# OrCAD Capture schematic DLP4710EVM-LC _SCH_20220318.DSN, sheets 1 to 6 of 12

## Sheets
1 P08: DLPC3479_VDD,VSS: size D; title: DLP4710EVM-LC
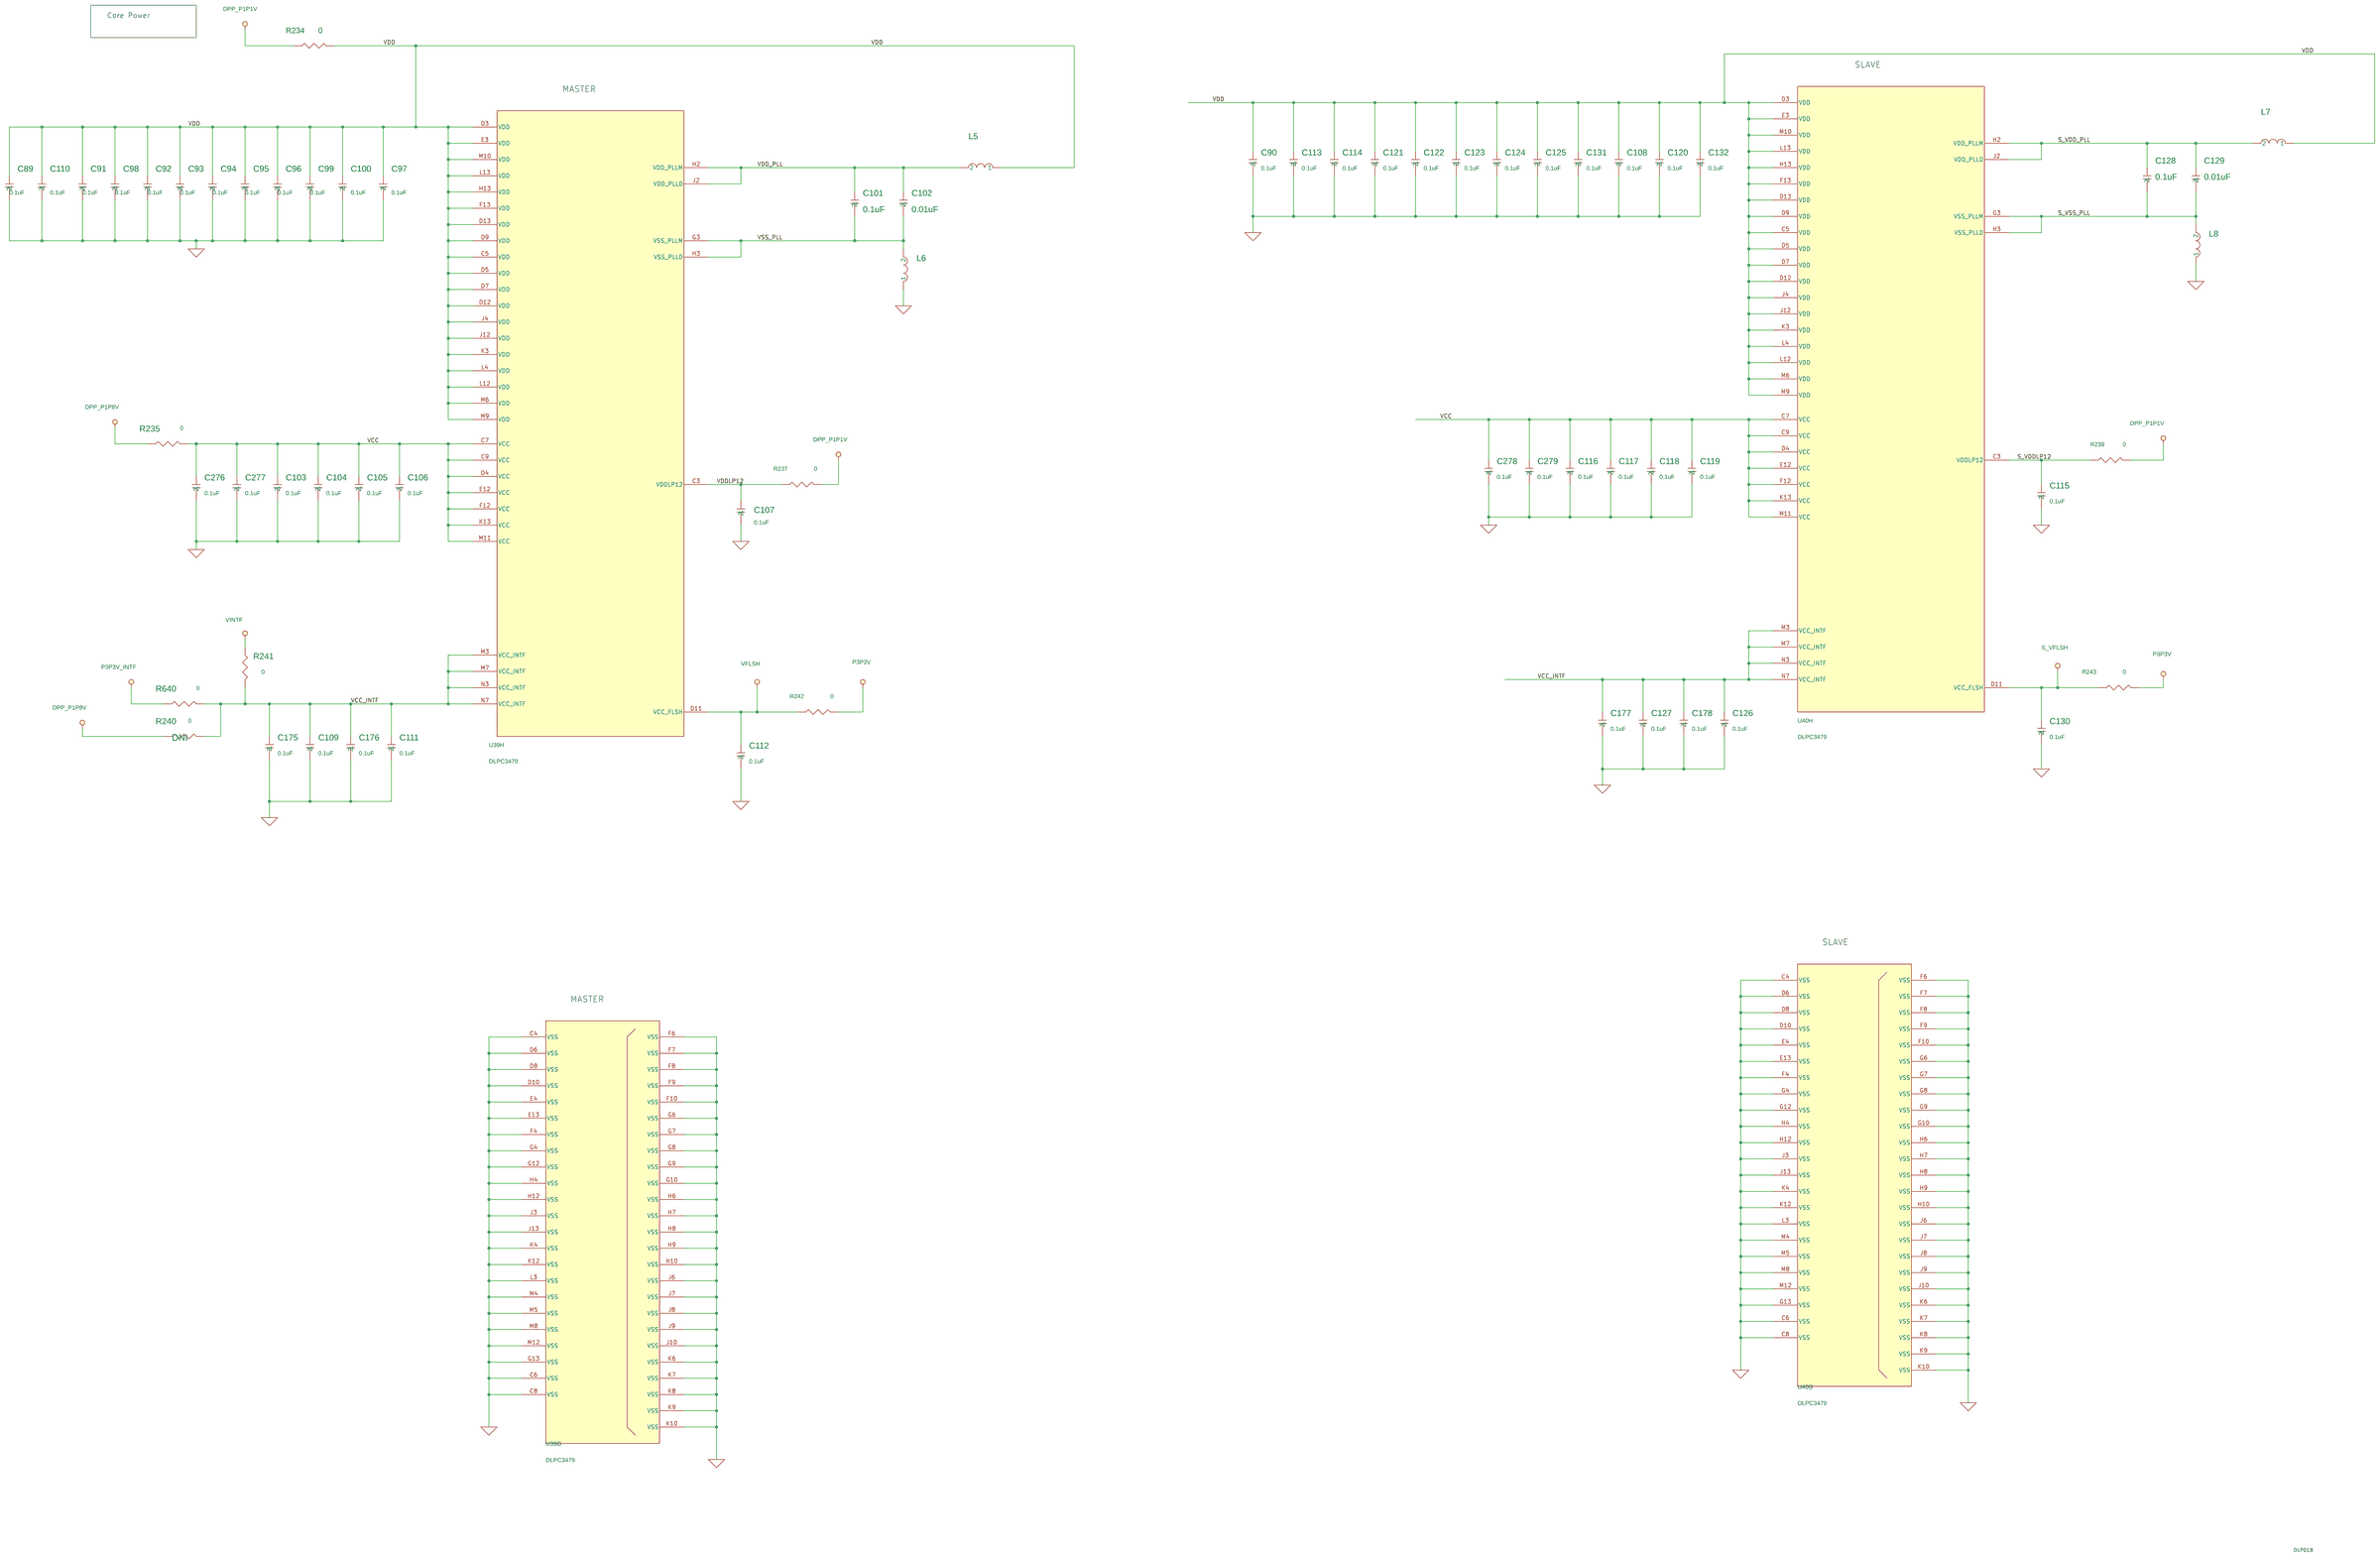
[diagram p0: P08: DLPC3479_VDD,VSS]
2 P09: MCU_MSP430: size D
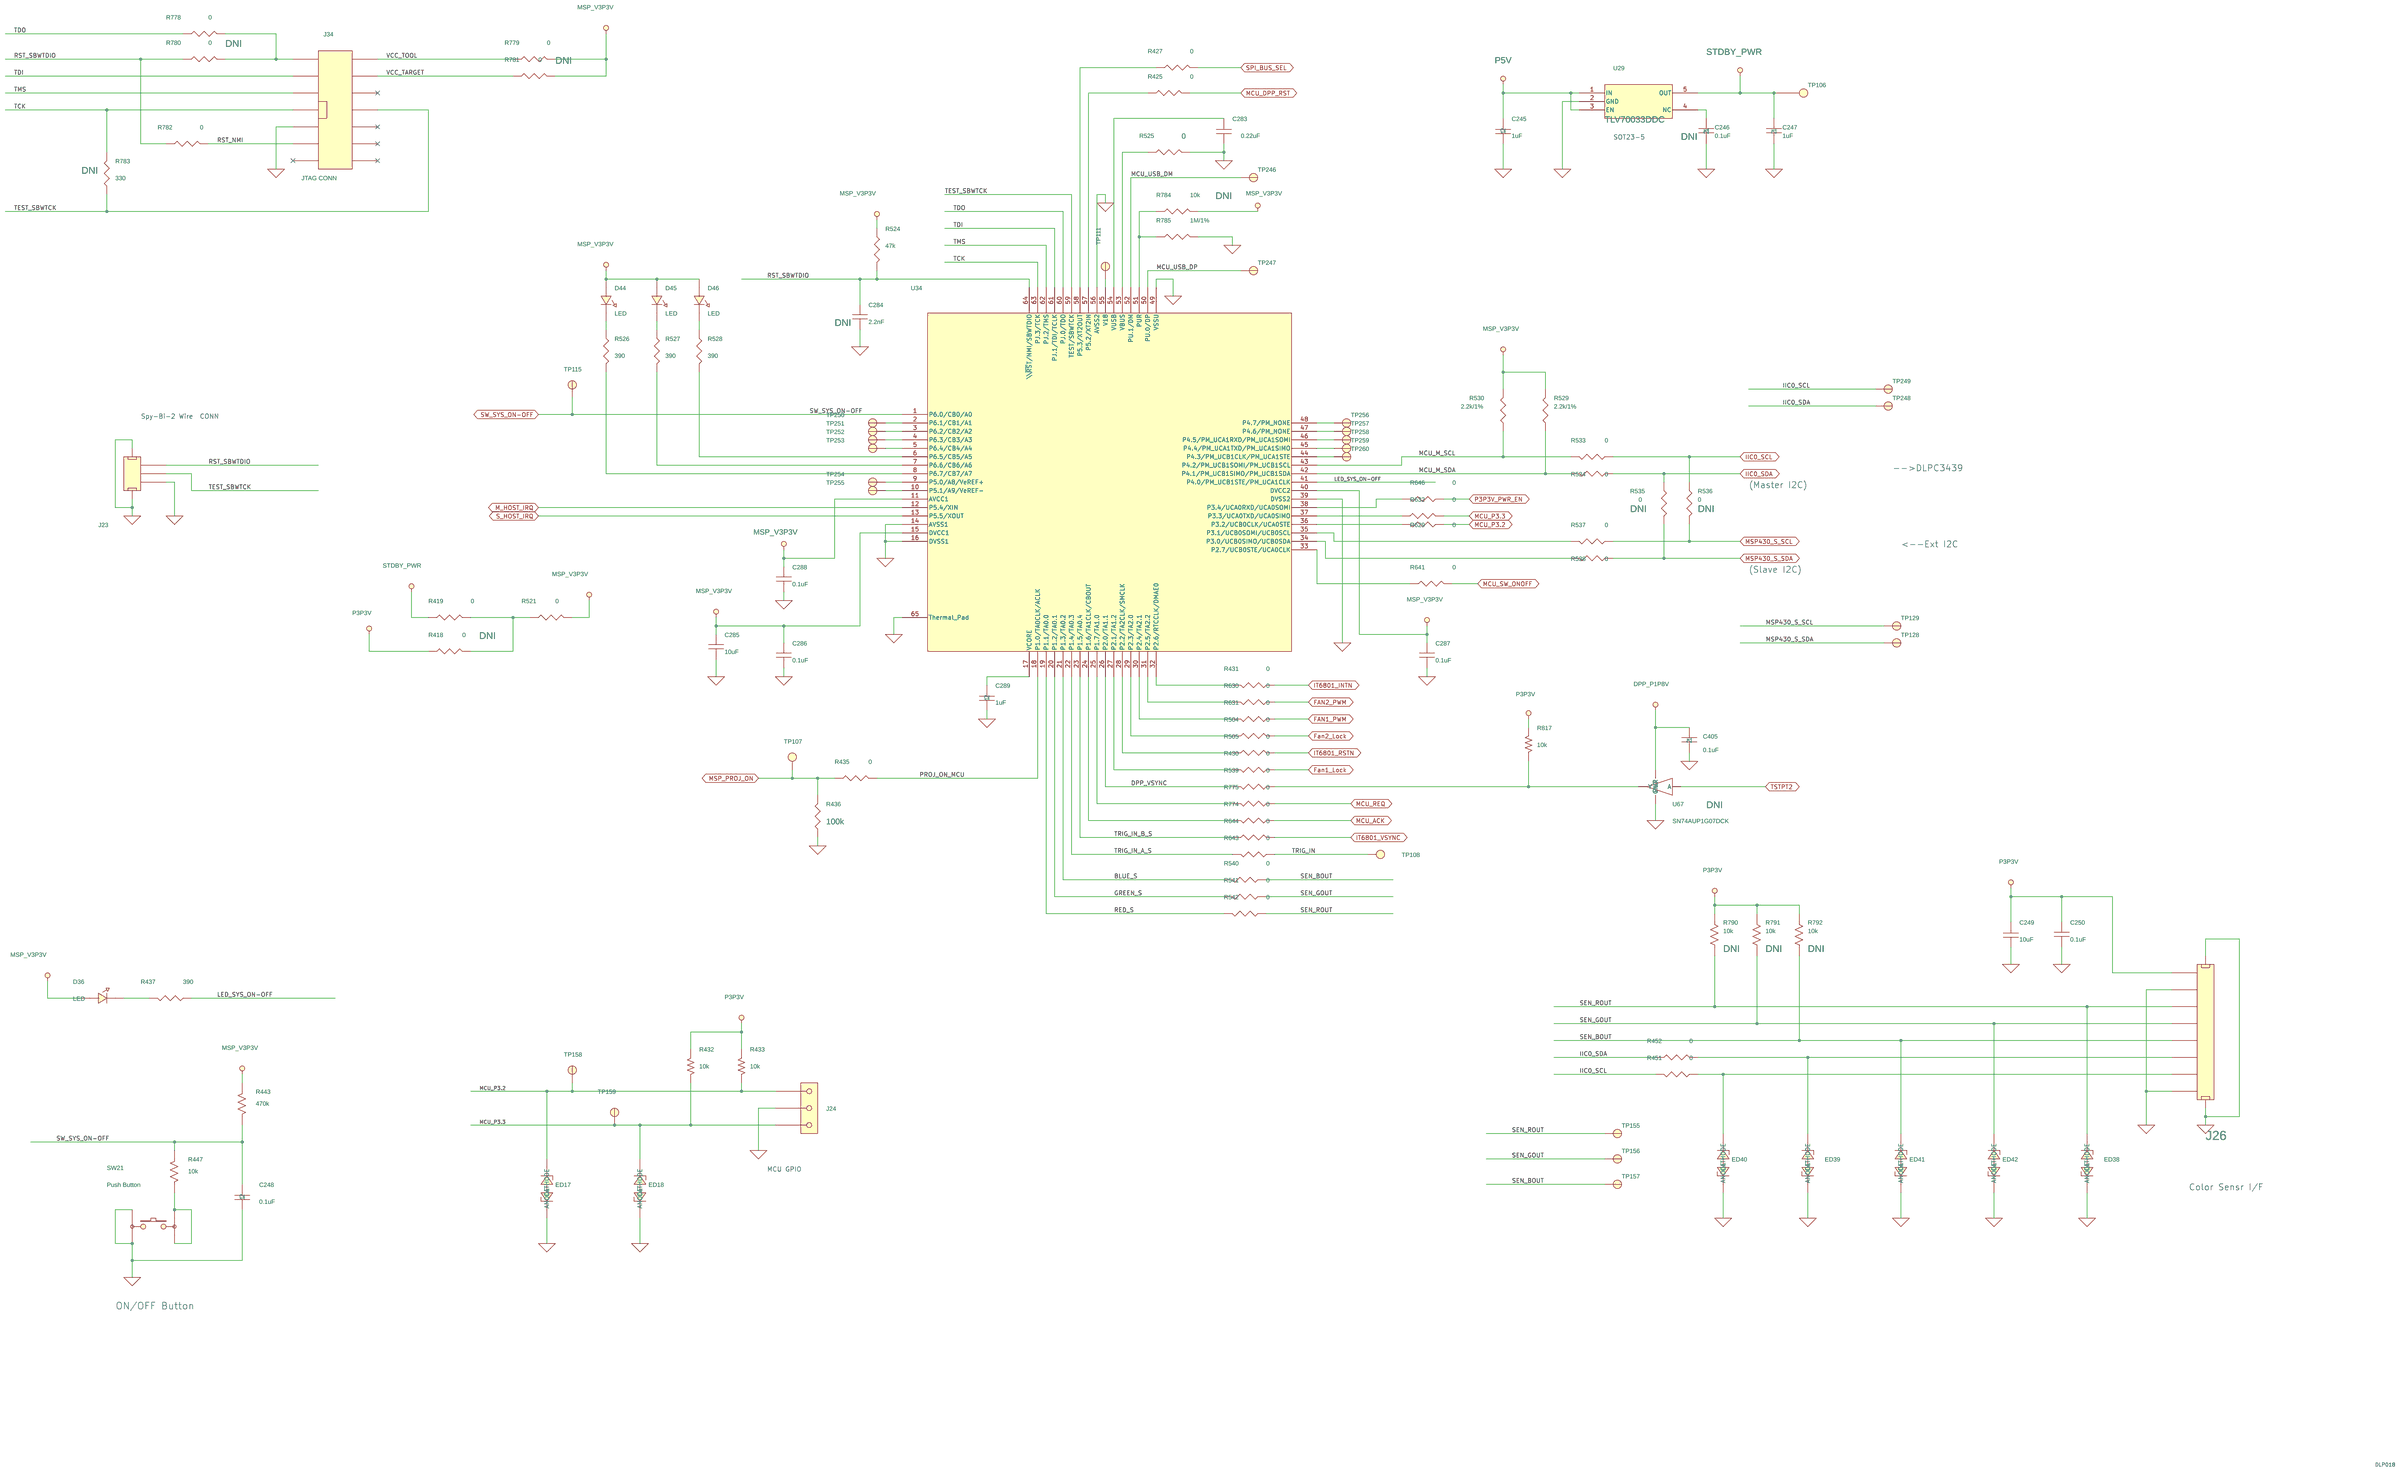
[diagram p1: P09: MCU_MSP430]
3 P01: History
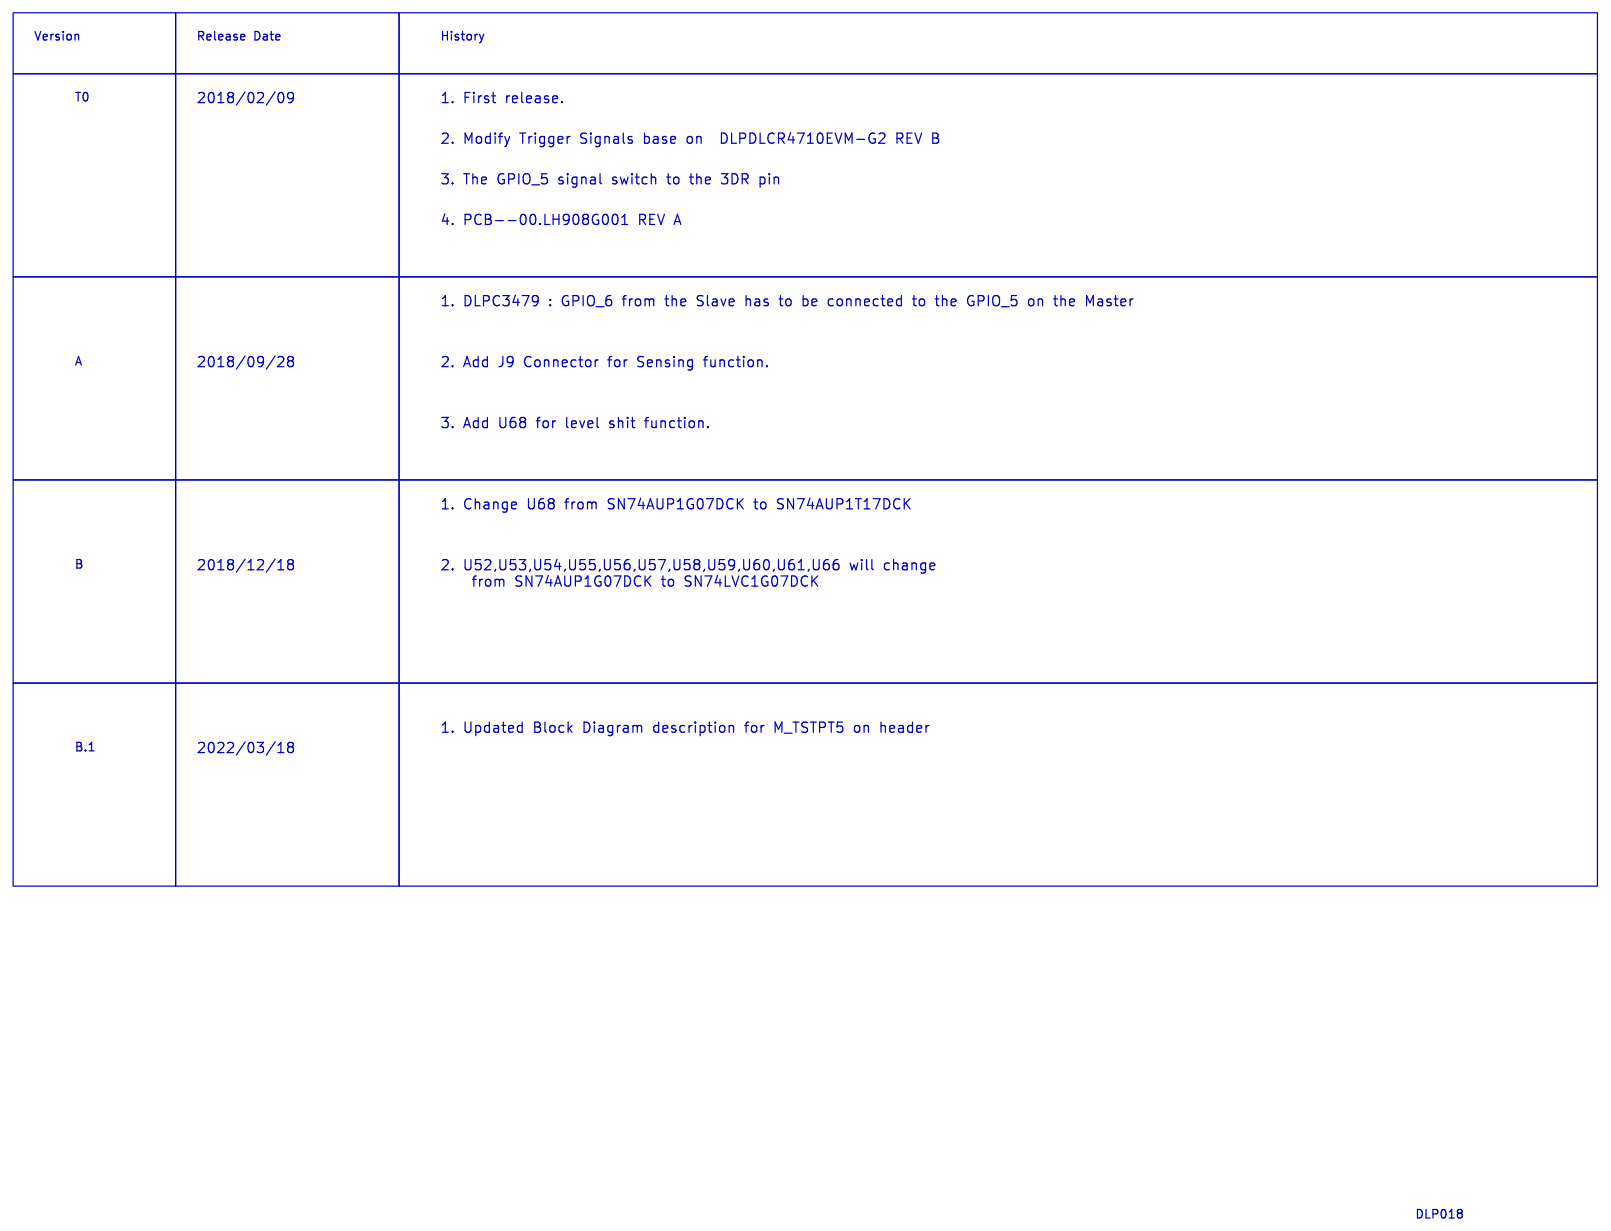
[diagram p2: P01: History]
4 P02: Block Diagram
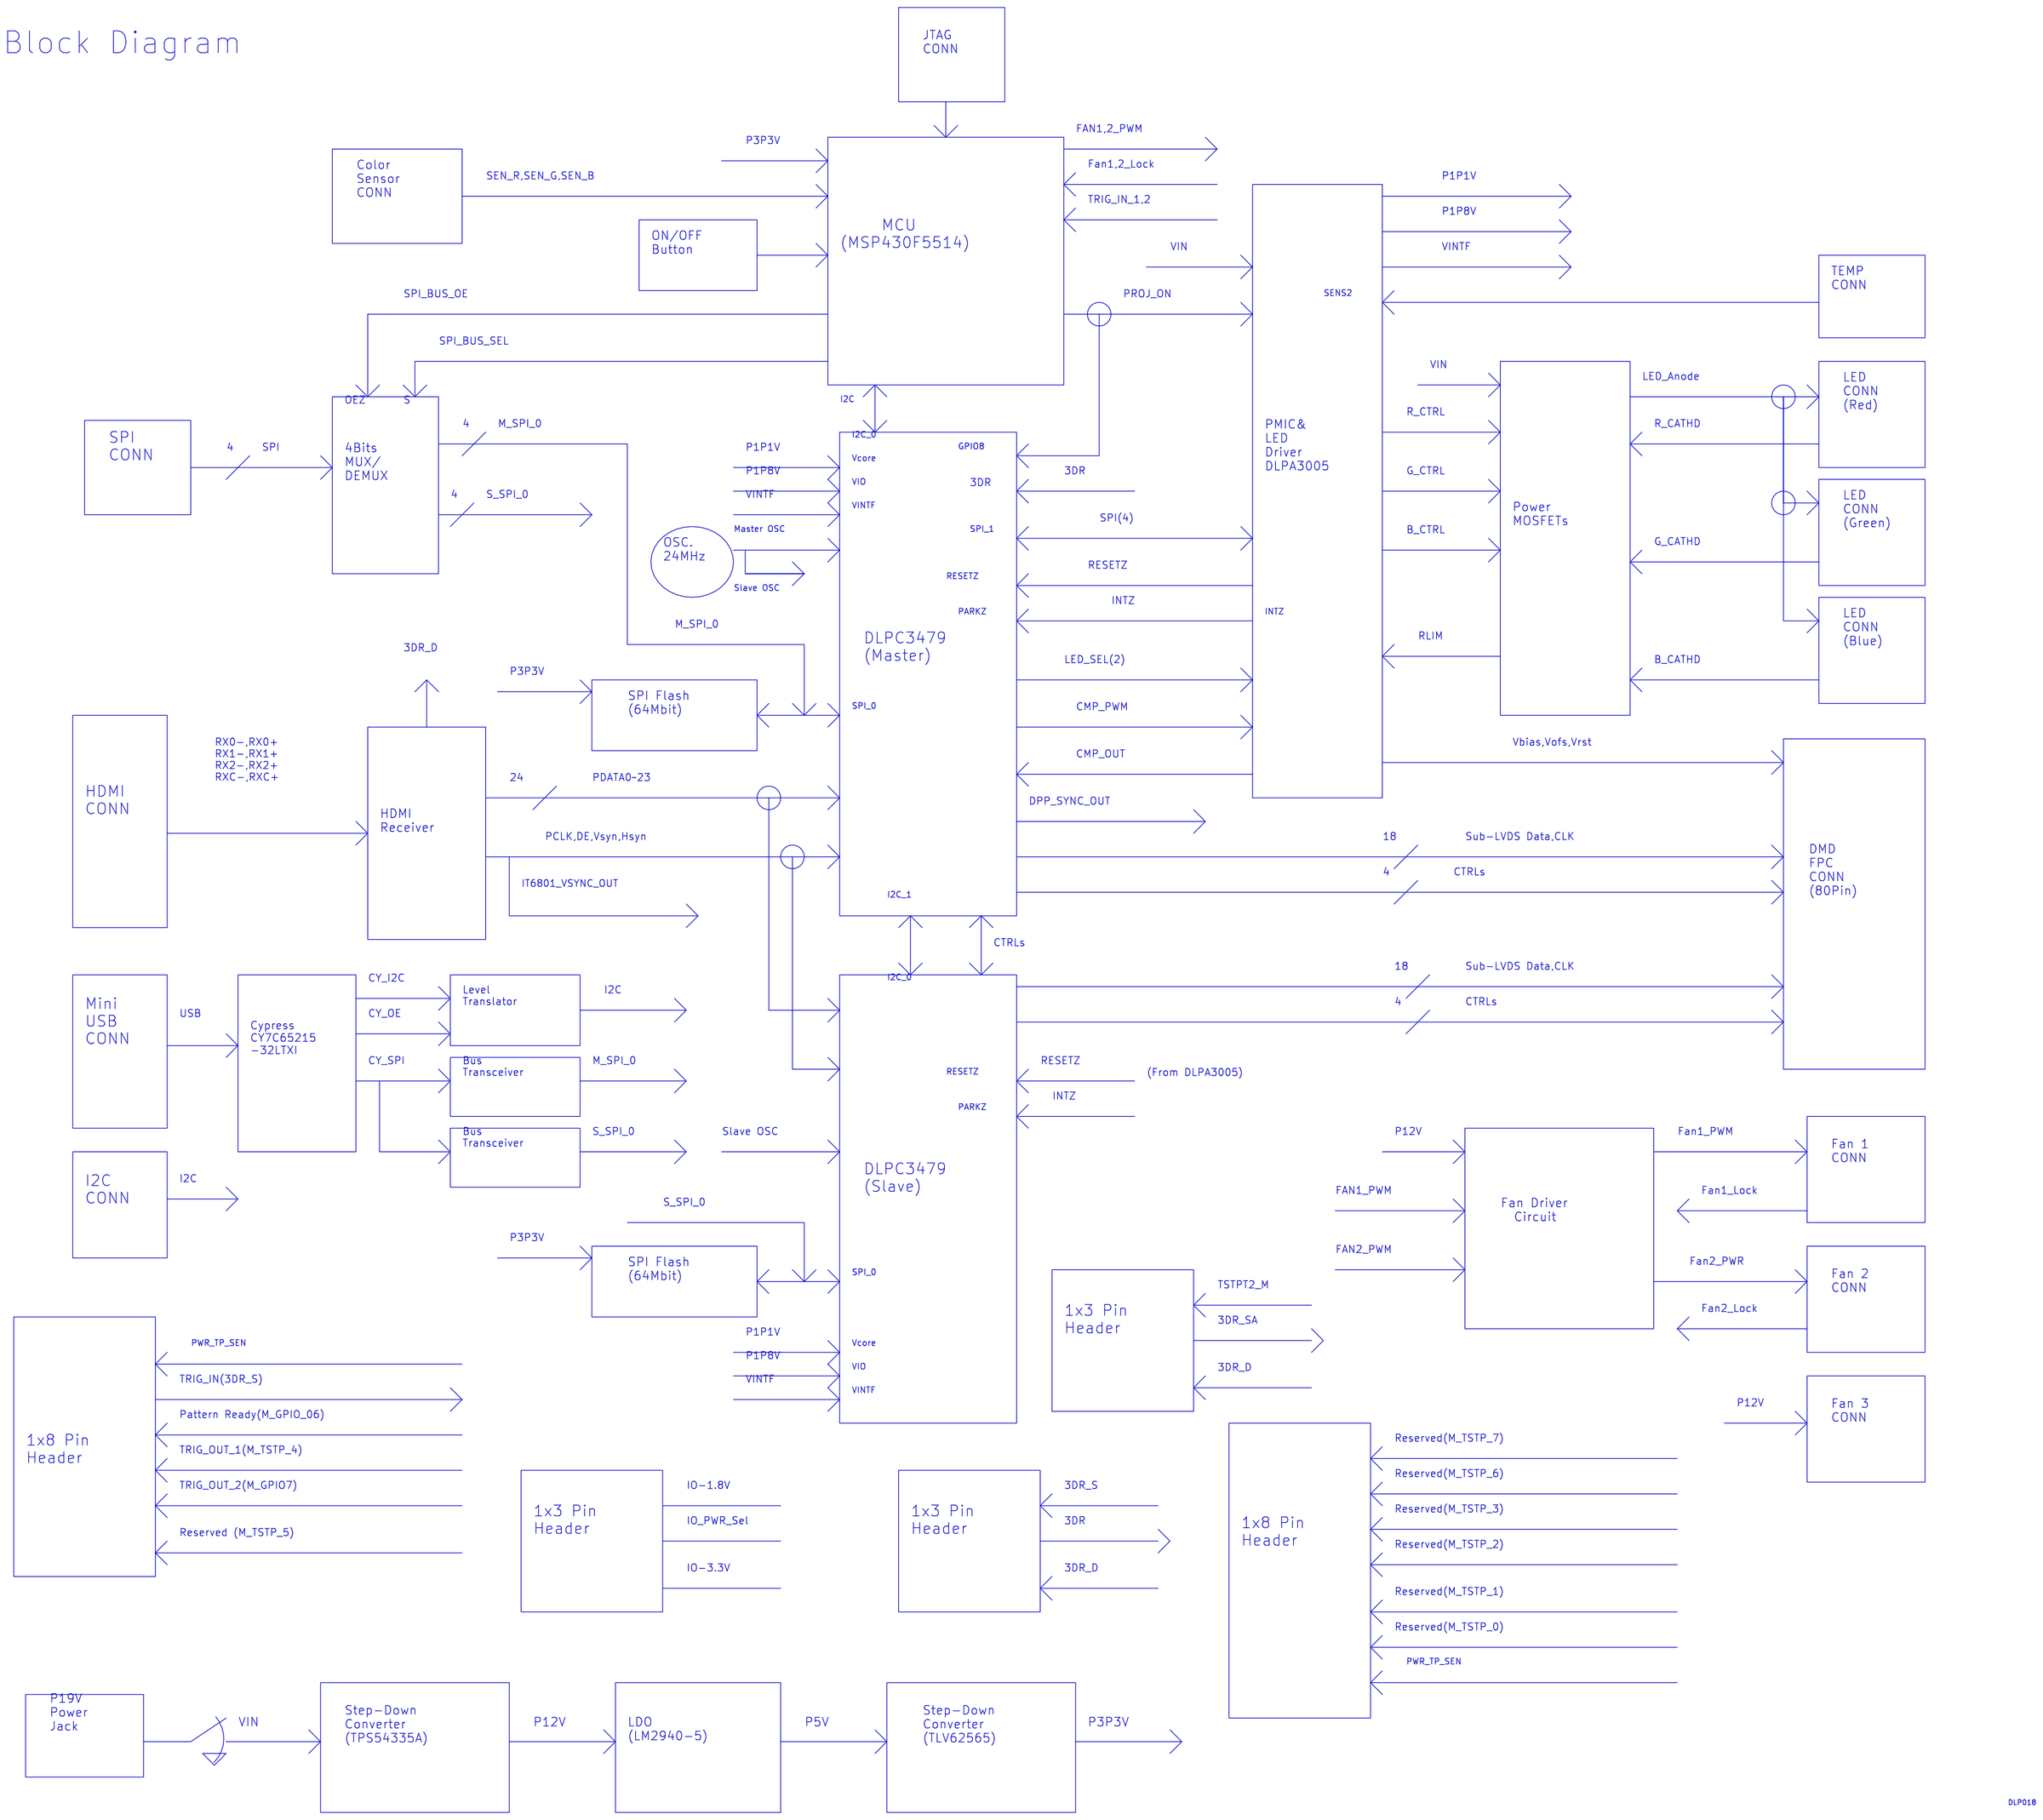
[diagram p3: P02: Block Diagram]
5 P07: DLPC3479_DMD Connector: size D
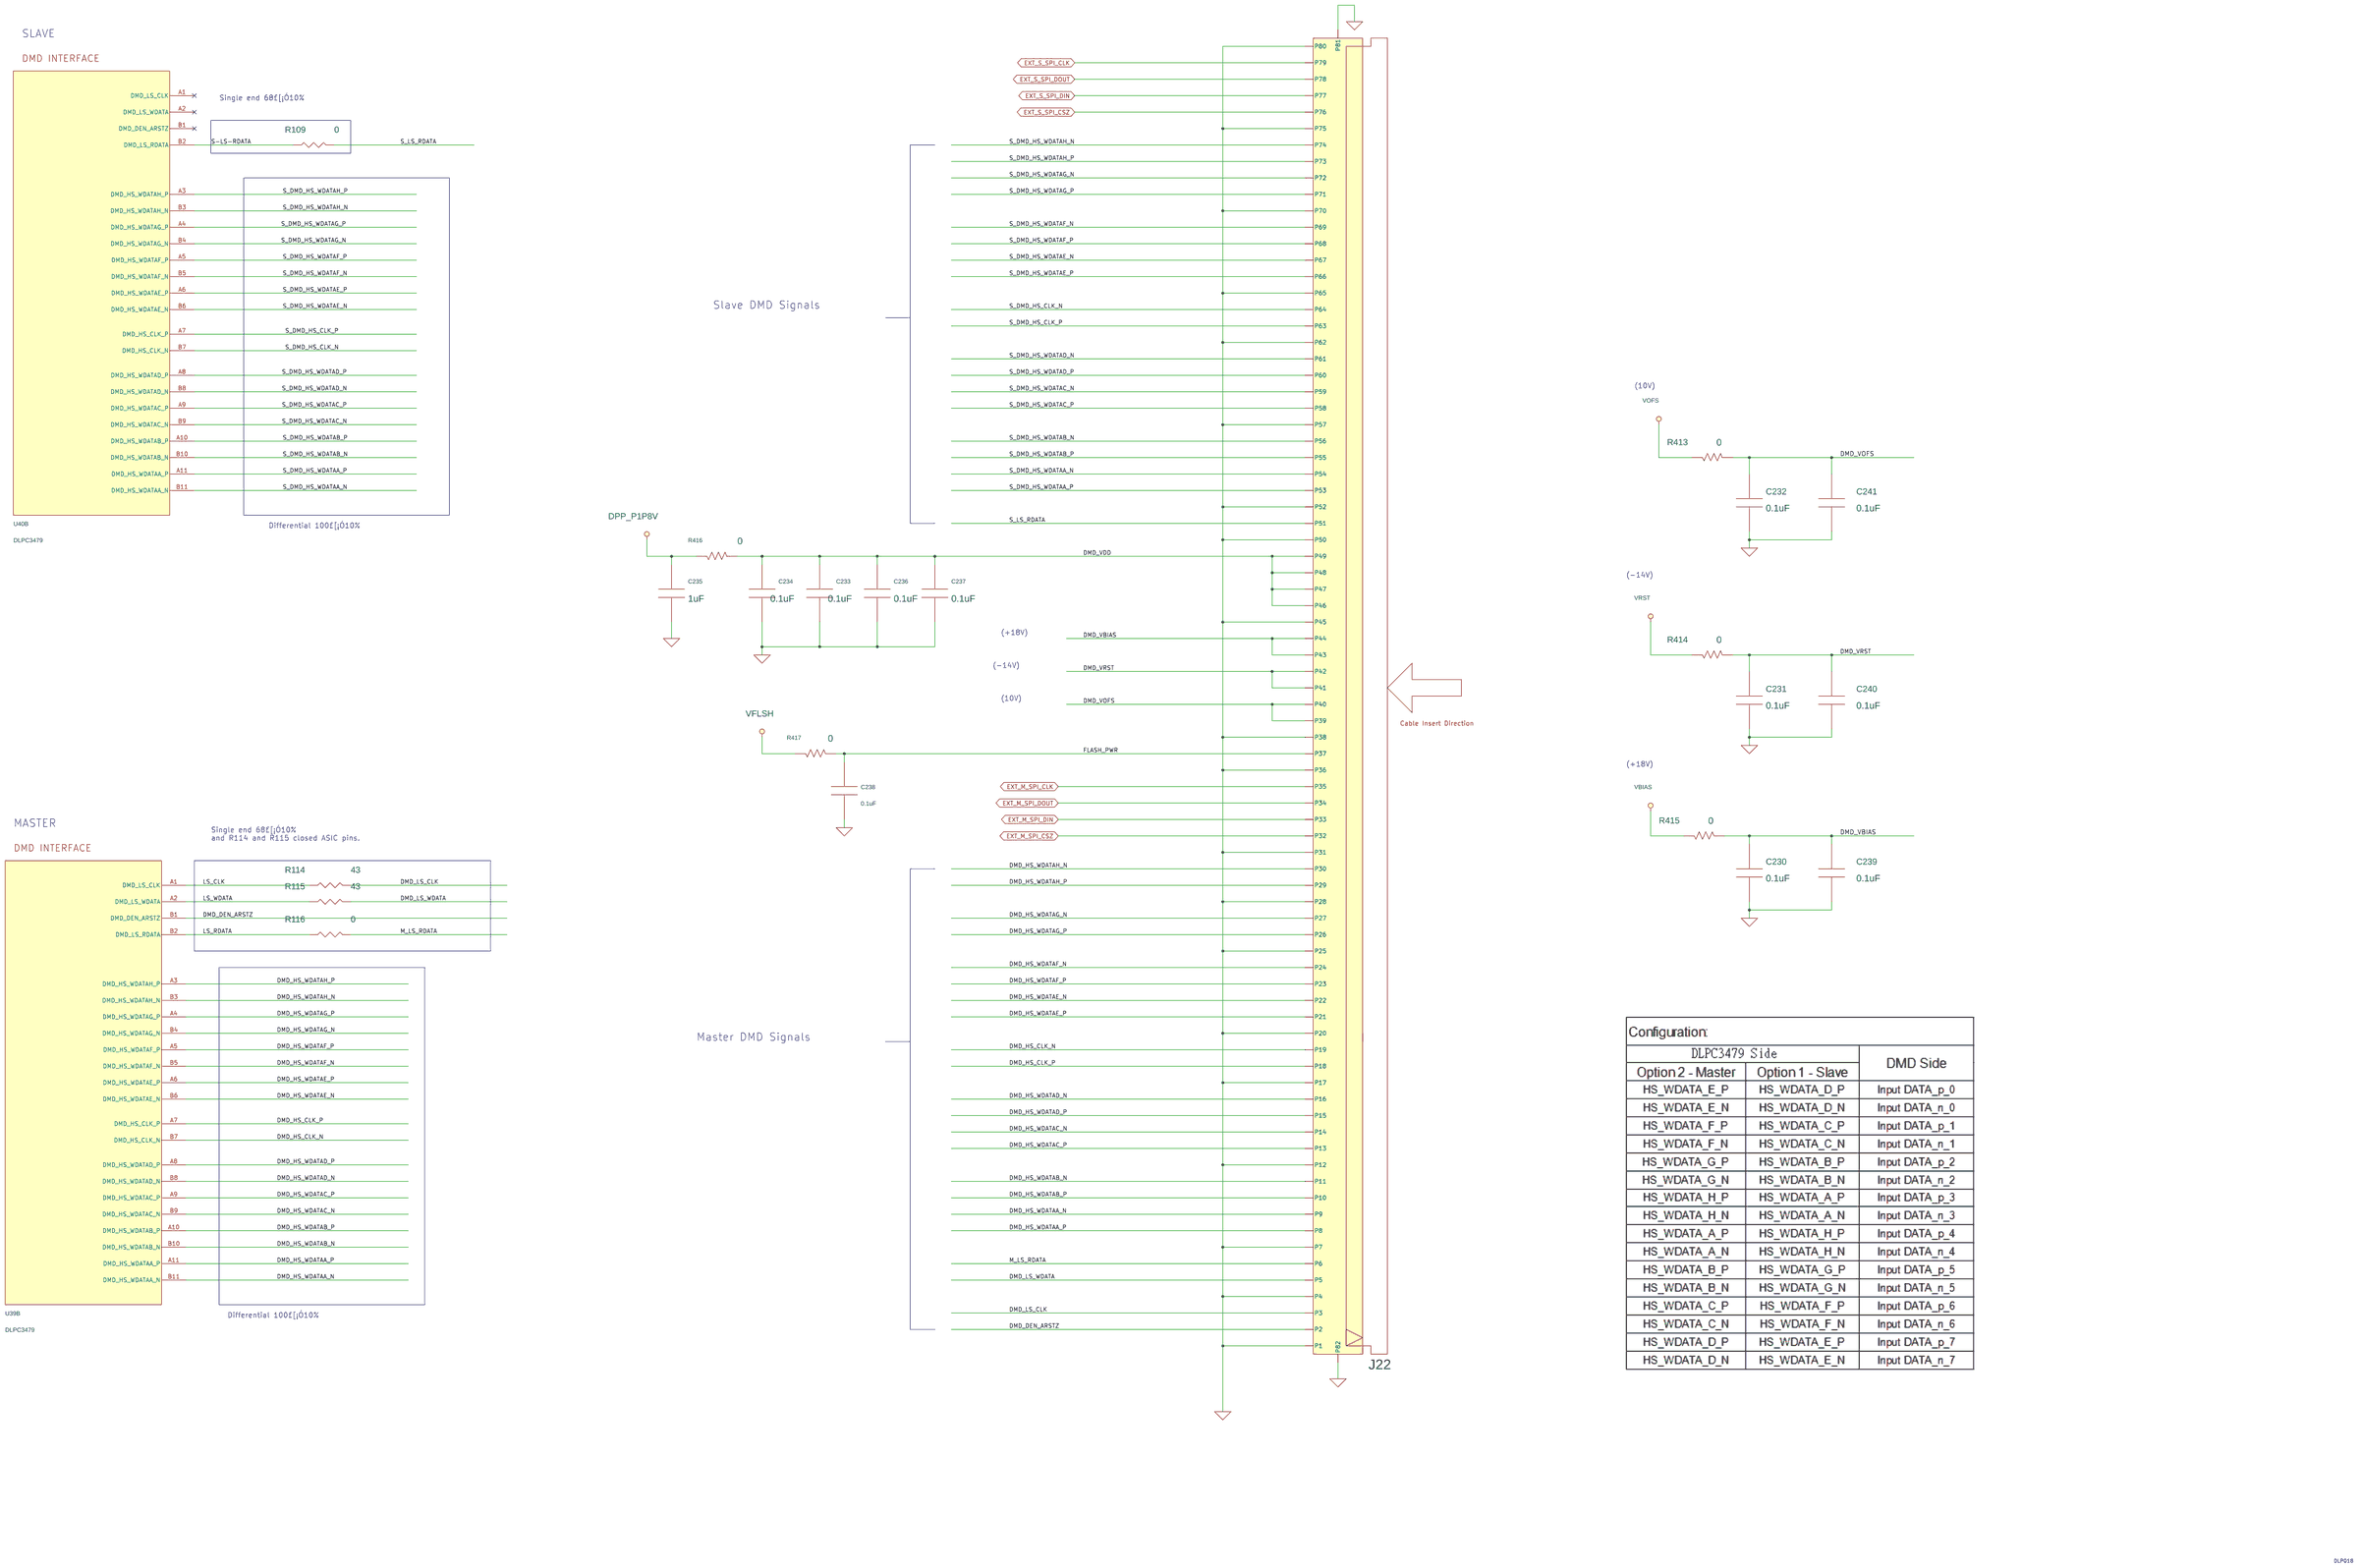
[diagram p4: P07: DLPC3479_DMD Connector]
6 P03: IT6801_HDMI Receiver: size D
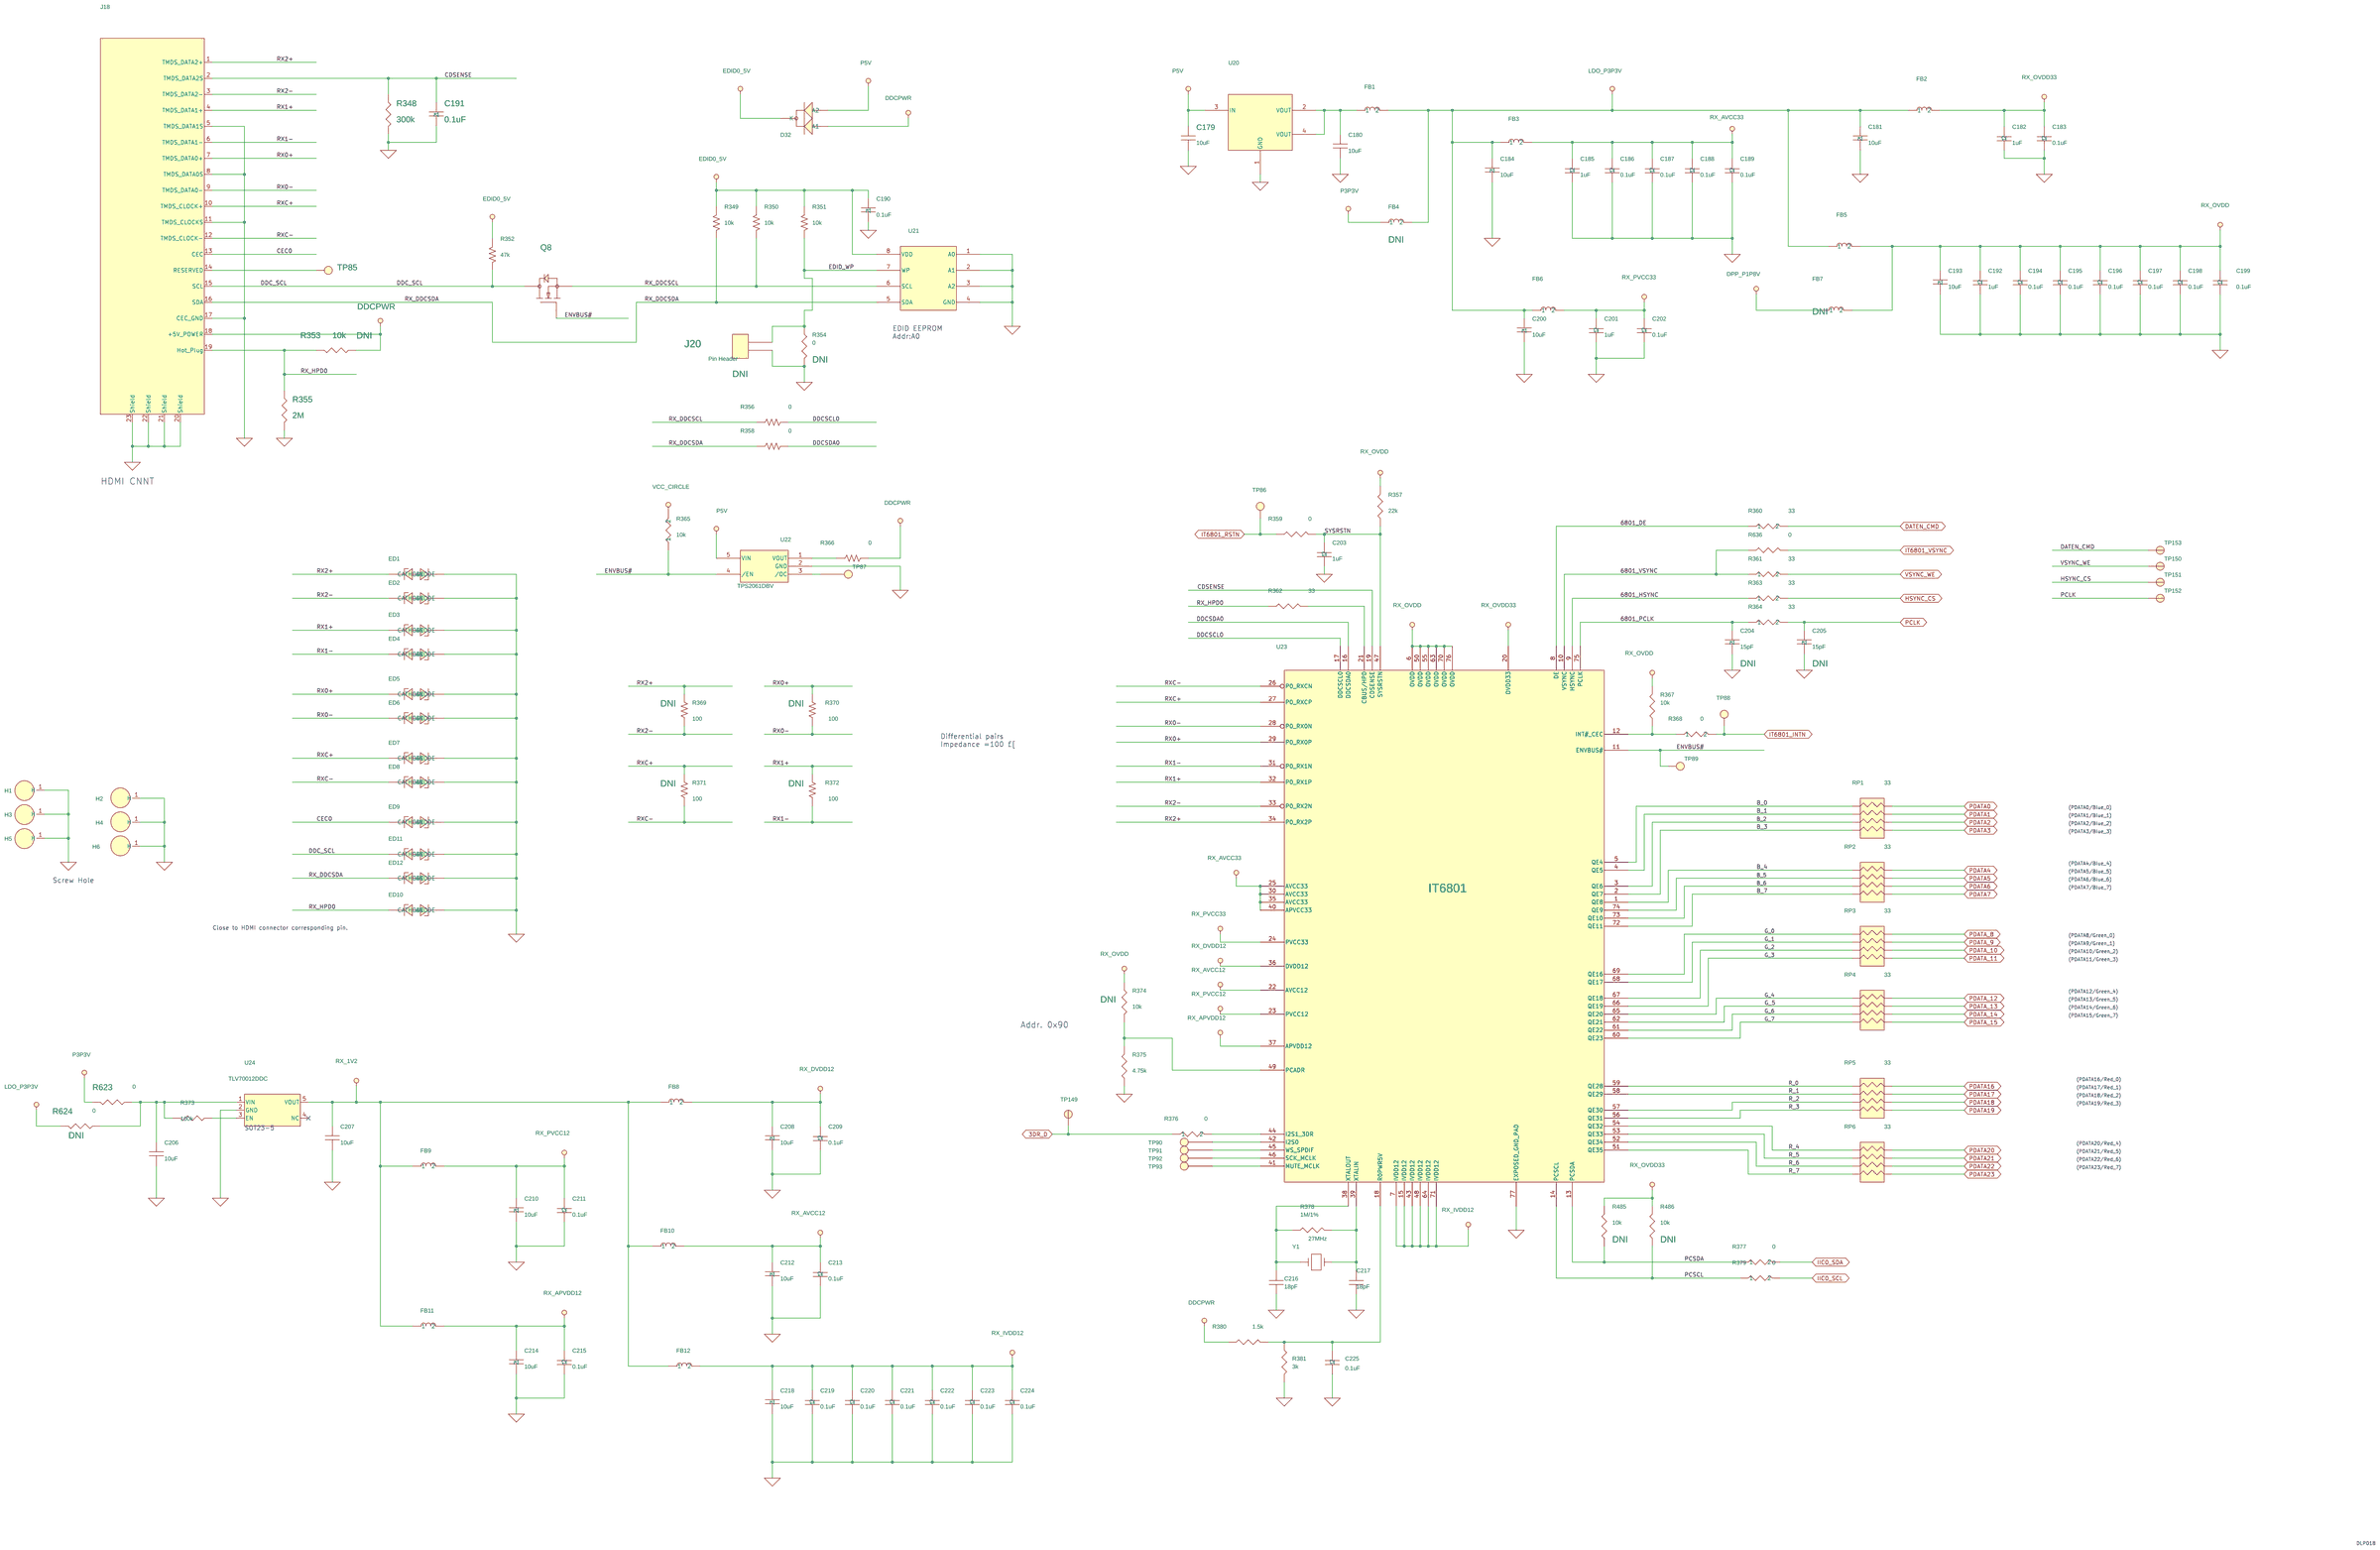
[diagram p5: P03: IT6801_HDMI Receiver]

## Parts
sheet P03: IT6801_HDMI Receiver
C179  10uF  [C0805\H1.35]
C180  10uF  [C0603\H0.9]
C181  10uF  [C0603\H0.9]
C182  1uF  [C0402\H0.55]
C183  0.1uF  [C0201\H0.33]
C184  10uF  [C0603\H0.9]
C185  1uF  [C0402\H0.55]
C186  0.1uF  [C0201\H0.33]
C187  0.1uF  [C0201\H0.33]
C188  0.1uF  [C0201\H0.33]
C189  0.1uF  [C0201\H0.33]
C190  0.1uF  [C0402\H0.55]
C191  0.1uF  [C0402\H0.55]
C192  1uF  [C0402\H0.55]
C193  10uF  [C0603\H0.9]
C194  0.1uF  [C0201\H0.33]
C195  0.1uF  [C0201\H0.33]
C196  0.1uF  [C0201\H0.33]
C197  0.1uF  [C0201\H0.33]
C198  0.1uF  [C0201\H0.33]
C199  0.1uF  [C0201\H0.33]
C200  10uF  [C0603\H0.9]
C201  1uF  [C0402\H0.55]
C202  0.1uF  [C0201\H0.33]
C203  1uF  [C0402\H0.55]
C204  15pF  [C0402\H0.55]
C205  15pF  [C0402\H0.55]
C206  10uF  [C0603\H0.9]
C207  10uF  [C0603\H0.9]
C208  10uF  [C0603\H0.9]
C209  0.1uF  [C0201\H0.33]
C210  10uF  [C0603\H0.9]
C211  0.1uF  [C0201\H0.33]
C212  10uF  [C0603\H0.9]
C213  0.1uF  [C0201\H0.33]
C214  10uF  [C0603\H0.9]
C215  0.1uF  [C0201\H0.33]
C216  18pF  [C0402\H0.55]
C217  18pF  [C0402\H0.55]
C218  10uF  [C0603\H0.9]
C219  0.1uF  [C0201\H0.33]
C220  0.1uF  [C0201\H0.33]
C221  0.1uF  [C0201\H0.33]
C222  0.1uF  [C0201\H0.33]
C223  0.1uF  [C0201\H0.33]
C224  0.1uF  [C0201\H0.33]
C225  0.1uF  [C0402\H0.55]
D32  BAT54CW  [MCP3\0.65\H1.1]
ED1  PESD5V0U1BL  [SOD882\2A1C\H0.5]
ED2  PESD5V0U1BL  [SOD882\2A1C\H0.5]
ED3  PESD5V0U1BL  [SOD882\2A1C\H0.5]
ED4  PESD5V0U1BL  [SOD882\2A1C\H0.5]
ED5  PESD5V0U1BL  [SOD882\2A1C\H0.5]
ED6  PESD5V0U1BL  [SOD882\2A1C\H0.5]
ED7  PESD5V0U1BL  [SOD882\2A1C\H0.5]
ED8  PESD5V0U1BL  [SOD882\2A1C\H0.5]
ED9  PESD5V0U1BL  [SOD882\2A1C\H0.5]
ED10  PESD5V0U1BL  [SOD882\2A1C\H0.5]
ED11  PESD5V0U1BL  [SOD882\2A1C\H0.5]
ED12  PESD5V0U1BL  [SOD882\2A1C\H0.5]
FB1  GMLB-160808  [L0603\H0.95]
FB2  GMLB-160808  [L0603\H0.95]
FB3  GMLB-160808  [L0603\H0.95]
FB4  GMLB-160808  [L0603\H0.95]
FB5  GMLB-160808  [L0603\H0.95]
FB6  GMLB-160808  [L0603\H0.95]
FB7  GMLB-160808  [L0603\H0.95]
FB8  GMLB-160808  [L0603\H0.95]
FB9  GMLB-160808  [L0603\H0.95]
FB10  GMLB-160808  [L0603\H0.95]
FB11  GMLB-160808  [L0603\H0.95]
FB12  GMLB-160808  [L0603\H0.95]
H1  H  [M2]
H2  H  [M2]
H3  H  [M2]
H4  H  [M2]
H5  H  [M2]
H6  H  [M2]
J18  47151-1101 MOLEX  [HDMI19\47151\0.5\H6.2]
J20  Pin Header  [SIP2\2.54]
Q8  DMN26D0UT  [SMCP3A\0.5\H0.9]
R348  300k  [R0402\H0.4]
R349  10k  [R0402\H0.4]
R350  10k  [R0402\H0.4]
R351  10k  [R0402\H0.4]
R352  47k  [R0402\H0.4]
R353  10k  [R0402\H0.4]
R354  0  [R0402\H0.4]
R355  2M  [R0402\H0.4]
R356  0  [R0402\H0.4]
R357  22k  [R0402\H0.4]
R358  0  [R0402\H0.4]
R359  0  [R0402\H0.4]
R360  33  [R0402\H0.4]
R361  33  [R0402\H0.4]
R362  33  [R0402\H0.4]
R363  33  [R0402\H0.4]
R364  33  [R0402\H0.4]
R365  10k  [R0402\H0.4]
R366  0  [R0402\H0.4]
R367  10k  [R0402\H0.4]
R368  0  [R0402\H0.4]
R369  100  [R0201\H0.3]
R370  100  [R0201\H0.3]
R371  100  [R0201\H0.3]
R372  100  [R0201\H0.3]
R373  100k  [R0402\H0.4]
R374  10k  [R0402\H0.4]
R375  4.75k  [R0402\H0.4]
R376  0  [R0402\H0.4]
R377  0  [R0402\H0.4]
R378  1M/1%  [R0402\H0.4]
R379  0  [R0402\H0.4]
R380  1.5k  [R0402\H0.4]
R381  3k  [R0402\H0.4]
R485  10k  [R0402\H0.4]
R486  10k  [R0402\H0.4]
R623  0  [R0402\H0.4]
R624  0  [R0402\H0.4]
R636  0  [R0402\H0.4]
RP1  33  [CR\0402\H0.5]
RP2  33  [CR\0402\H0.5]
RP3  33  [CR\0402\H0.5]
RP4  33  [CR\0402\H0.5]
RP5  33  [CR\0402\H0.5]
RP6  33  [CR\0402\H0.5]
TP85  Testpoint  [ICT_50]
TP86  Testpoint  [ICT_50]
TP87  Testpoint  [ICT_50]
TP88  Testpoint  [ICT_50]
TP89  Testpoint  [ICT_50]
TP90  Testpoint  [ICT_50]
TP91  Testpoint  [ICT_50]
TP92  Testpoint  [ICT_50]
TP93  Testpoint  [ICT_50]
TP149  Testpoint  [ICT_50]
TP150  Testpoint  [ICT_50]
TP151  Testpoint  [ICT_50]
TP152  Testpoint  [ICT_50]
TP153  Testpoint  [ICT_50]
U20  LM1117IMPX-3.3/NOPB  [SOT223\2.3\H1.8]
U21  24LC02  [SOP8\1.27\H1.75]
U22  TPS2061DBV  [CP5\0.95\H1.45]
U23  IT6801  [QFN76\9X9\T\0.4\H0.9]
U24  TLV70012DDC  [CP5\0.95\H1.3]
Y1  27MHz  [CRYS2\5X3.2\H1]
sheet P07: DLPC3479_DMD Connector
C230  0.1uF  [C0402\H0.55]
C231  0.1uF  [C0402\H0.55]
C232  0.1uF  [C0402\H0.55]
C233  0.1uF  [C0402\H0.55]
C234  0.1uF  [C0402\H0.55]
C235  1uF  [C0402\H0.55]
C236  0.1uF  [C0402\H0.55]
C237  0.1uF  [C0402\H0.55]
C238  0.1uF  [C0402\H0.55]
C239  0.1uF  [C0402\H0.55]
C240  0.1uF  [C0402\H0.55]
C241  0.1uF  [C0402\H0.55]
J22  104060-8017 Molex  [FPC80\104060\0.5\H2.7]
R109  0  [R0402\H0.4]
R114  43  [R0402\H0.4]
R115  43  [R0402\H0.4]
R116  0  [R0402\H0.4]
R413  0  [R0402\H0.4]
R414  0  [R0402\H0.4]
R415  0  [R0402\H0.4]
R416  0  [R0402\H0.4]
R417  0  [R0402\H0.4]
sheet P08: DLPC3479_VDD,VSS
C89  0.1uF  [C0201\H0.33]
C90  0.1uF  [C0201\H0.33]
C91  0.1uF  [C0201\H0.33]
C92  0.1uF  [C0201\H0.33]
C93  0.1uF  [C0201\H0.33]
C94  0.1uF  [C0201\H0.33]
C95  0.1uF  [C0201\H0.33]
C96  0.1uF  [C0201\H0.33]
C97  0.1uF  [C0201\H0.33]
C98  0.1uF  [C0201\H0.33]
C99  0.1uF  [C0201\H0.33]
C100  0.1uF  [C0201\H0.33]
C101  0.1uF  [C0201\H0.33]
C102  0.01uF  [C0402\H0.55]
C103  0.1uF  [C0201\H0.33]
C104  0.1uF  [C0201\H0.33]
C105  0.1uF  [C0201\H0.33]
C106  0.1uF  [C0201\H0.33]
C107  0.1uF  [C0201\H0.33]
C108  0.1uF  [C0201\H0.33]
C109  0.1uF  [C0201\H0.33]
C110  0.1uF  [C0201\H0.33]
C111  0.1uF  [C0201\H0.33]
C112  0.1uF  [C0201\H0.33]
C113  0.1uF  [C0201\H0.33]
C114  0.1uF  [C0201\H0.33]
C115  0.1uF  [C0201\H0.33]
C116  0.1uF  [C0201\H0.33]
C117  0.1uF  [C0201\H0.33]
C118  0.1uF  [C0201\H0.33]
C119  0.1uF  [C0201\H0.33]
C120  0.1uF  [C0201\H0.33]
C121  0.1uF  [C0201\H0.33]
C122  0.1uF  [C0201\H0.33]
C123  0.1uF  [C0201\H0.33]
C124  0.1uF  [C0201\H0.33]
C125  0.1uF  [C0201\H0.33]
C126  0.1uF  [C0201\H0.33]
C127  0.1uF  [C0201\H0.33]
C128  0.1uF  [C0201\H0.33]
C129  0.01uF  [C0402\H0.55]
C130  0.1uF  [C0201\H0.33]
C131  0.1uF  [C0201\H0.33]
C132  0.1uF  [C0201\H0.33]
C175  0.1uF  [C0201\H0.33]
C176  0.1uF  [C0201\H0.33]
C177  0.1uF  [C0201\H0.33]
C178  0.1uF  [C0201\H0.33]
C276  0.1uF  [C0201\H0.33]
C277  0.1uF  [C0201\H0.33]
C278  0.1uF  [C0201\H0.33]
C279  0.1uF  [C0201\H0.33]
L5  GMLB-160808  [L0603\H0.95]
L6  GMLB-160808  [L0603\H0.95]
L7  GMLB-160808  [L0603\H0.95]
L8  GMLB-160808  [L0603\H0.95]
R234  0  [R0402\H0.4]
R235  0  [R0402\H0.4]
R237  0  [R0402\H0.4]
R239  0  [R0402\H0.4]
R240  0  [R0402\H0.4]
R241  0  [R0402\H0.4]
R242  0  [R0402\H0.4]
R243  0  [R0402\H0.4]
R640  0  [R0402\H0.4]
U39  DLPC3479  [VFBGA201\0.8\H1]  (sections A,B,C,D,E,F,G,H)
U40  DLPC3479  [VFBGA201\0.8\H1]  (sections A,B,C,D,E,F,G,H)
sheet P09: MCU_MSP430
C245  1uF  [C0402\H0.55]
C246  0.1uF  [C0402\H0.55]
C247  1uF  [C0402\H0.55]
C248  0.1uF  [C0402\H0.55]
C249  10uF  [C0603\H0.9]
C250  0.1uF  [C0402\H0.55]
C283  0.22uF  [C0603\H0.9]
C284  2.2nF  [C0201\H0.33]
C285  10uF  [C0603\H0.9]
C286  0.1uF  [C0402\H0.55]
C287  0.1uF  [C0402\H0.55]
C288  0.1uF  [C0402\H0.55]
C289  1uF  [C0402\H0.55]
C405  0.1uF  [C0402\H0.55]
D36  LED  [LED2S\16-213\1X0.5\H0.45]
D44  LED  [LED2S\16-213\1X0.5\H0.45]
D45  LED  [LED2S\16-213\1X0.5\H0.45]
D46  LED  [LED2S\16-213\1X0.5\H0.45]
ED17  PESD5V0U1BL  [SOD882\2A1C\H0.5]
ED18  PESD5V0U1BL  [SOD882\2A1C\H0.5]
ED38  PESD5V0U1BL  [SOD882\2A1C\H0.5]
ED39  PESD5V0U1BL  [SOD882\2A1C\H0.5]
ED40  PESD5V0U1BL  [SOD882\2A1C\H0.5]
ED41  PESD5V0U1BL  [SOD882\2A1C\H0.5]
ED42  PESD5V0U1BL  [SOD882\2A1C\H0.5]
J23  S3B-ZR-SM4A-TF(LF)(SN)  [TU1501_3S_90\1.5\H3.7]
J24  B3B-ZR(LF)(SN) JST  [TU1501_3D_180\1.5\H4.5]
J26  053261-0871 Molex  [TU1252_8S_90\1.25\H3.4]
J34  JTAG CONN  [HEADER7X2\2.54L\H9.15]
R418  0  [R0402\H0.4]
R419  0  [R0402\H0.4]
R425  0  [R0402\H0.4]
R427  0  [R0402\H0.4]
R430  0  [R0402\H0.4]
R431  0  [R0402\H0.4]
R432  10k  [R0402\H0.4]
R433  10k  [R0402\H0.4]
R435  0  [R0402\H0.4]
R436  100k  [R0402\H0.4]
R437  390  [R0402\H0.4]
R443  470k  [R0402\H0.4]
R447  10k  [R0402\H0.4]
R451  0  [R0402\H0.4]
R452  0  [R0402\H0.4]
R504  0  [R0402\H0.4]
R505  0  [R0402\H0.4]
R521  0  [R0402\H0.4]
R524  47k  [R0402\H0.4]
R525  0  [R0402\H0.4]
R526  390  [R0402\H0.4]
R527  390  [R0402\H0.4]
R528  390  [R0402\H0.4]
R529  2.2k/1%  [R0402\H0.4]
R530  2.2k/1%  [R0402\H0.4]
R533  0  [R0402\H0.4]
R534  0  [R0402\H0.4]
R535  0  [R0402\H0.4]
R536  0  [R0402\H0.4]
R537  0  [R0402\H0.4]
R538  0  [R0402\H0.4]
R539  0  [R0402\H0.4]
R540  0  [R0402\H0.4]
R541  0  [R0402\H0.4]
R542  0  [R0402\H0.4]
R629  0  [R0402\H0.4]
R630  0  [R0402\H0.4]
R631  0  [R0402\H0.4]
R632  0  [R0402\H0.4]
R641  0  [R0402\H0.4]
R643  0  [R0402\H0.4]
R644  0  [R0402\H0.4]
R646  0  [R0402\H0.4]
R774  0  [R0402\H0.4]
R775  0  [R0402\H0.4]
R778  0  [R0402\H0.4]
R779  0  [R0402\H0.4]
R780  0  [R0402\H0.4]
R781  0  [R0402\H0.4]
R782  0  [R0402\H0.4]
R783  330  [R0402\H0.4]
R784  10k  [R0402\H0.4]
R785  1M/1%  [R0402\H0.4]
R790  10k  [R0402\H0.4]
R791  10k  [R0402\H0.4]
R792  10k  [R0402\H0.4]
R817  10k  [R0402\H0.4]
SW21  Push Button  [SW4S\STS-D5\H7]
TP106  Testpoint  [ICT_50]
TP107  Testpoint  [ICT_50]
TP108  Testpoint  [ICT_50]
TP111  Testpoint  [ICT_50]
TP115  Testpoint  [ICT_50]
TP128  Testpoint  [ICT_50]
TP129  Testpoint  [ICT_50]
TP155  Testpoint  [ICT_50]
TP156  Testpoint  [ICT_50]
TP157  Testpoint  [ICT_50]
TP158  Testpoint  [ICT_50]
TP159  Testpoint  [ICT_50]
TP246  Testpoint  [ICT_50]
TP247  Testpoint  [ICT_50]
TP248  Testpoint  [ICT_50]
TP249  Testpoint  [ICT_50]
TP250  Testpoint  [ICT_50]
TP251  Testpoint  [ICT_50]
TP252  Testpoint  [ICT_50]
TP253  Testpoint  [ICT_50]
TP254  Testpoint  [ICT_50]
TP255  Testpoint  [ICT_50]
TP256  Testpoint  [ICT_50]
TP257  Testpoint  [ICT_50]
TP258  Testpoint  [ICT_50]
TP259  Testpoint  [ICT_50]
TP260  Testpoint  [ICT_50]
U29  TLV70033DDC  [CP5\0.95\H1.3]
U34  MSP430F5514IRGC  [QFN64\RGC\0.5\H1]
U67  SN74AUP1G07DCK  [MCP5\0.65\H1.1]

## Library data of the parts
C179 C288 = CAP_NP_5: ID: 114026; device: C0805
C180 = CAP_NP_1: ID: 114026; device: C0805
C181 = CAP_0.1uF_0603_35: Ceramic CAP X7R 6.3V 0.1uF
C182 = CAP_0.1uF_0603_31: Ceramic CAP X7R 6.3V 0.1uF
C183 = CAP_0.1uF_0603_18: Ceramic CAP X7R 6.3V 0.1uF
C184 = CAP_0.1uF_0603_39: Ceramic CAP X7R 6.3V 0.1uF
C185 = CAP_0.1uF_0603_36: Ceramic CAP X7R 6.3V 0.1uF
C186 = CAP_0.1uF_0603_3: Ceramic CAP X7R 6.3V 0.1uF
C187 = CAP_0.1uF_0603_20: Ceramic CAP X7R 6.3V 0.1uF
C188 = CAP_0.1uF_0603_30: Ceramic CAP X7R 6.3V 0.1uF
C189 = CAP_0.1uF_0603_25: Ceramic CAP X7R 6.3V 0.1uF
C190 C248 = CAP_0.1uF_0603: Ceramic CAP X7R 6.3V 0.1uF
C191 = CAP_0.1uF_0603_17: Ceramic CAP X7R 6.3V 0.1uF
C192 = CAP_0.1uF_0603_38: Ceramic CAP X7R 6.3V 0.1uF
C193 = CAP_0.1uF_0603_10: Ceramic CAP X7R 6.3V 0.1uF
C194 = CAP_0.1uF_0603_11: Ceramic CAP X7R 6.3V 0.1uF
C195 = CAP_0.1uF_0603_19: Ceramic CAP X7R 6.3V 0.1uF
C196 = CAP_0.1uF_0603_22: Ceramic CAP X7R 6.3V 0.1uF
C197 = CAP_0.1uF_0603_26: Ceramic CAP X7R 6.3V 0.1uF
C198 = CAP_0.1uF_0603_29: Ceramic CAP X7R 6.3V 0.1uF
C199 = CAP_0.1uF_0603_37: Ceramic CAP X7R 6.3V 0.1uF
C200 = CAP_0.1uF_0603_12: Ceramic CAP X7R 6.3V 0.1uF
C201 C289 = CAP_0.1uF_0603_4: Ceramic CAP X7R 6.3V 0.1uF
C202 = CAP_0.1uF_0603_15: Ceramic CAP X7R 6.3V 0.1uF
C203 = CAP_0.1uF_0603_16: Ceramic CAP X7R 6.3V 0.1uF
C204 = CAP_0.1uF_0603_24: Ceramic CAP X7R 6.3V 0.1uF; DNI: DNI
C205 = CAP_0.1uF_0603_1: Ceramic CAP X7R 6.3V 0.1uF; DNI: DNI
C206 C287 = CAP_NP: ID: 114026; device: C0805
C207 = CAP_NP_3: ID: 114026; device: C0805
C208 = CAP_0.1uF_0603_7: Ceramic CAP X7R 6.3V 0.1uF
C209 = CAP_0.1uF_0603_13: Ceramic CAP X7R 6.3V 0.1uF
C210 = CAP_0.1uF_0603_21: Ceramic CAP X7R 6.3V 0.1uF
C211 = CAP_0.1uF_0603_33: Ceramic CAP X7R 6.3V 0.1uF
C212 C247 = CAP_0.1uF_0603_5: Ceramic CAP X7R 6.3V 0.1uF
C213 = CAP_0.1uF_0603_9: Ceramic CAP X7R 6.3V 0.1uF
C214 = CAP_0.1uF_0603_27: Ceramic CAP X7R 6.3V 0.1uF
C215 = CAP_0.1uF_0603_34: Ceramic CAP X7R 6.3V 0.1uF
C216 = CAP_NP_2
C217 = CAP_NP_4
C218 = CAP_0.1uF_0603_28: Ceramic CAP X7R 6.3V 0.1uF
C219 = CAP_0.1uF_0603_32: Ceramic CAP X7R 6.3V 0.1uF
C220 = CAP_0.1uF_0603_40: Ceramic CAP X7R 6.3V 0.1uF
C221 C405 = CAP_0.1uF_0603_2: Ceramic CAP X7R 6.3V 0.1uF
C222 = CAP_0.1uF_0603_6: Ceramic CAP X7R 6.3V 0.1uF
C223 = CAP_0.1uF_0603_14: Ceramic CAP X7R 6.3V 0.1uF
C224 = CAP_0.1uF_0603_8: Ceramic CAP X7R 6.3V 0.1uF
C225 = CAP_0.1uF_0603_23: Ceramic CAP X7R 6.3V 0.1uF
D32 = BAV70_SOT_0: BAV70 SOT23 BY PAN JIT; A/I?: SMT; PART ID: 93L  64 42  P
ED1-ED12 ED17 ED18 ED38-ED42 = DIODE_SCHOTTKY31_4
FB1 = FB_4: ID: 159352; device: R0603
FB2 = FB_11: ID: 159352; device: R0603
FB3 = FB_2: ID: 159352; device: R0603
FB4 = FB_9: DNI: DNI; ID: 159352; device: R0603
FB5 = FB_7: ID: 159352; device: R0603
FB6 = FB_10: ID: 159352; device: R0603
FB7 = FB: DNI: DNI; ID: 159352; device: R0603
FB8 = FB_3: ID: 159352; device: R0603
FB9 = FB_6: ID: 159352; device: R0603
FB10 = FB_1: ID: 159352; device: R0603
FB11 = FB_8: ID: 159352; device: R0603
FB12 = FB_5: ID: 159352; device: R0603
H1-H6 = H
J18 = HDMI_2
J20 = CON2_v2: DNI: DNI
Q8 = 2N7002
R109 R114-R116 R234 R235 R237 R239 R241-R243 R348 R355 R373 R419 R425 R427 R430 R431 R435 R436 R504 R505 R521 R525 R623 R636 R640 R641 R643 R644 R646 R785 = RESISTOR_SM
R349 R817 = R_v4_1
R350 = R_v4_7
R351 R432 = R_v4
R352 = R_v4_9
R240 R353 R418 R624 R784 = RESISTOR_SM: DNI: DNI
R354 = R_10: DNI: DNI
R356 = R_v4_8
R357 = R_8
R358 = R_v4_10
R359 = R_2
R360 = RESISTOR_3_4
R361 = RESISTOR_3_2
R362 = R
R363 = RESISTOR_3_3
R364 = RESISTOR_3_1
R365 = RESISTOR_2
R366 = R_v4_6
R367 = R_4
R368 = RESISTOR_3
R369 = R_v4_2: DNI: DNI
R370 = R_v4_3: DNI: DNI
R371 = R_v4_4: DNI: DNI
R372 = R_v4_5: DNI: DNI
R374 = R_1: DNI: DNI
R375 = R_7
R376 = RESISTOR_3_5
R377 = RESISTOR_3_6
R378 R437 R524 R526-R528 R533 R534 R537-R542 R629-R632 = RESISTOR
R379 = RESISTOR_3_7
R380 = R_3
R381 = R_9
R485 = R_6: DNI: DNI
R486 = R_5: DNI: DNI
RP1-RP6 = RESARR_IS_4_SM
TP85 TP86 TP88 TP89 TP107 TP108 = T_POINT_R: Desc: TEST POINT, T/H, BLACK; Dist: Digi-Key; Dist p/n: 5001K-ND; Mfr: Keystone Electronics; Mfr p/n: 5001
TP87 TP90-TP93 TP106 = Testpoint
TP111 TP115 TP128 TP129 TP149-TP153 TP155-TP159 TP246-TP260 = EM,TESTPOINT: Install: DNI; MFG: -- NOT A PART --; Part Specific: TP_20RD10; Type: testpoint via; Vendor: -- NOT A PART --
U20 = 2.5VTO1_0.8V: ID: 136117; device: SOT223
U21 = F_0
U22 = TPS2061DBV
U23 = IT6801_3
U24 = RP103K131D_5
Y1 = CRY_1
C230-C232 C239-C241 = PAS,CAP,NP,large: DigiKey: 587-1456-1-ND; DigiReel: 587-1456-6-ND; Family: passive; Index PN: 922; Lead Style: SMT; MFG: Taiyo Yuden; Material: x5r; P/D_NUM: TMK105BJ104KV-F; Part Number: TMK105BJ104KV-F; Part Specific: CAP CER .10UF 25V X5R 0402; Type: capacitor; VENDOR: Taiyo Yuden; VPC: 25V
C233 C234 C236-C238 = PAS,CAP,NP,large: DigiKey: 445-4952-1-ND; DigiReel: 445-4952-6-ND; Family: passive; Index PN: 681; Lead Style: SMT; MFG: TDK; Material: x7r; P/D_NUM: C1005X7R1C104K050BC; Part Number: C1005X7R1C104K050BC; Part Specific: CAP CER .1UF 16V X7R 0402; TOLERANCE: 10%; Type: capacitor; VENDOR: TDK; VPC: 16V
C235 = PAS,CAP,NP,large: DigiKey: 445-4952-1-ND; DigiReel: 445-4952-6-ND; Family: passive; Index PN: 681; Lead Style: SMT; MFG: TDK; Material: x7r; P/D_NUM: C1005X7R1C104K050BC; Part Number: C1005X7R1C104K050BC; TOLERANCE: 10%; Type: capacitor; VENDOR: TDK; VPC: 16V
J22 = EM,CONN,80P,1R,FLEX,2X_8: DigiKey: HFV080CT-ND; DigiReel: HFV080DKR-ND; Family: electro/mechanical; Lead Style: SMT; MFG: Hirose; P/D_NUM: FPC CNNT; Part Number: FH28H-80S-0.5SH(05); Part Specific: CONN FPC 80POS 0.5MM SMD GOLD; Pin Cnt: 80; Pin Spacing: 0.5mm; Type: connector; Vendor: Hirose
R413-R417 = PAS,R,large: DigiKey: P15979CT-ND; DigiReel: P15979DKR-ND; Family: passive; Index PN: 1178; Lead Style: SMT; MFG: Panasonic; Material: chip; P/D_NUM: ERJ-1GN0R00C; Part Number: ERJ-1GN0R00C; Part Specific: RES 0.0 OHM 1/20W 0201 SMD; Type: resistor; VENDOR: Panasonic; VPC: 1/20W
C89 = C_1_13
C90 = C_1_7
C91 = C_1_1
C92 = C_1_51
C93 = C_1_21
C94 = C_1_37
C95 = C_1
C96 = C_1_22
C97 = C_1_2
C98 = C_1_34
C99 = C_1_30
C100 = C_1_9
C101 = C_1_6
C102 = C_1_24
C103 = C_1_47
C104 = C_1_14
C105 = C_1_49
C106 = C_1_40
C107 = C_1_50
C108 = C_1_28
C109 = C_1_31
C110 = C_1_18
C111 = C_1_44
C112 = C_1_35
C113 = C_1_11
C114 = C_1_15
C115 = C_1_5
C116 = C_1_29
C117 = C_1_32
C118 = C_1_38
C119 = C_1_42
C120 = C_1_20
C121 = C_1_25
C122 = C_1_36
C123 = C_1_41
C124 = C_1_45
C125 = C_1_48
C126 = C_1_33
C127 = C_1_4
C128 = C_1_12
C129 = C_1_27
C130 = C_1_19
C131 = C_1_3
C132 = C_1_8
C175 = C_1_17
C176 = C_1_16
C177 = C_1_39
C178 = C_1_10
C276 = C_1_46
C277 = C_1_43
C278 = C_1_23
C279 = C_1_26
L5 = INDUCTOR_0_3: INDUCTOR; Package: SMD 1210; Vendor: Taiyo Yuden/Any
L6 = INDUCTOR_0_1: INDUCTOR; Package: SMD 1210; Vendor: Taiyo Yuden/Any
L7 = INDUCTOR_0: INDUCTOR; Package: SMD 1210; Vendor: Taiyo Yuden/Any
L8 = INDUCTOR_0_2: INDUCTOR; Package: SMD 1210; Vendor: Taiyo Yuden/Any
U39 = TIDLP,DPP3438_6: DigiKey: ---; DigiReel: ---; Family: processor; Index PN: 1176; Install: Y; Lead Style: SMT; MFG: Texas Instruments; P/D_NUM: 2512737-0092; Package: Master; Part Number: 2512737-0092; Part Specific: IC, DPP3439 ASIC, DLP-PICO PROCESSOR; Type: dlp; Vendor: Texas Instruments
U40 = TIDLP,DPP3438_6: DigiKey: ---; DigiReel: ---; Family: processor; Index PN: 1176; Install: Y; Lead Style: SMT; MFG: Texas Instruments; P/D_NUM: 2512737-0092; Package: Slave; Part Number: 2512737-0092; Part Specific: IC, DPP3439 ASIC, DLP-PICO PROCESSOR; Type: dlp; Vendor: Texas Instruments
C245 = CAP_0.1uF_0603_1: Ceramic CAP X7R 6.3V 0.1uF
C246 = CAP_0.1uF_0603_3: Ceramic CAP X7R 6.3V 0.1uF; DNI: DNI
C249 = CAP_NP_3
C250 = CAP_NP_2: Capacitor; MFG: AVX; Part Number: 0603YC104KAT2A; RATING: 25V; SOURCE: DIGI 478-1239-1-ND; TOLERANCE: 10%; Type: X7R
C283 = CAP_NP_1: ID: 114026; device: C0603
C284 = CAP_NP_4: DNI: DNI; ID: 114026; device: C0805
C285 = CAP_NP_6: ID: 114026; device: C0805
C286 = CAP_NP_7: ID: 114026; device: C0805
D36 D44-D46 = DSEI20_TO_0
J23 = CONN_SOCKET_3_3
J24 = 3_PIN_Connector_3: Package: NC/TU1501WNV-04; SPEC.1: 1A
J26 = CONN_PCB_6-R_2
J34 = CON14AP_1
R433 = R_v4_2
R443 R447 = RESISTOR_H_TOL_1: P/D_NUM: ERJ-1GEJ300C; TOLERANCE: 5%; VENDOR: Panasonic; VPC: ?
R451 = R_5: Resistor; ICA_MFR_NAME: PANASONIC; ICA_PARTNUM: $$1785048$$ERJ-3GSYJ102; MFG: Ralec; Part Number: RTT02103JTH; RATING: 1/10W; SOURCE: DIGI P20.0LCT-ND; TOLERANCE: 5%
R452 = R_7: Resistor; ICA_MFR_NAME: PANASONIC; ICA_PARTNUM: $$1785048$$ERJ-3GSYJ102; MFG: Ralec; Part Number: RTT02103JTH; RATING: 1/10W; SOURCE: DIGI P20.0LCT-ND; TOLERANCE: 5%
R529 R530 = R_1: Tolerance: 1%
R535 R536 = RESISTOR: DNI: DNI
R774 = R_8: ROHS CHIP RES  1/16W 150K 5% SMT 0402; P/N: 01.00036G503
R775 = R_9: ROHS CHIP RES  1/16W 150K 5% SMT 0402; P/N: 01.00036G503
R778 = R: ROHS CHIP RES  1/16W 150K 5% SMT 0402; P/N: 01.00036G503
R779 = R_3: ROHS CHIP RES  1/16W 150K 5% SMT 0402; P/N: 01.00036G503
R780 = R_1: ROHS CHIP RES  1/16W 150K 5% SMT 0402; DNI: DNI; P/N: 01.00036G503
R781 = R_6: ROHS CHIP RES  1/16W 150K 5% SMT 0402; DNI: DNI; P/N: 01.00036G503
R782 = R_2: ROHS CHIP RES  1/16W 150K 5% SMT 0402; P/N: 01.00036G503
R783 = R_4: ROHS CHIP RES  1/16W 150K 5% SMT 0402; DNI: DNI; P/N: 01.00036G503
R790-R792 = RESISTOR_H_TOL_1: DNI: DNI; P/D_NUM: MCR006YZPF1000; TOLERANCE: 1%; VENDOR: Rohm; VPC: ?
SW21 = SW_PUSHBUTTON-SPST-2_SM
U29 = TPS71518DCK_3
U34 = MSP430F2232|RHA_4
U67 = TMP_0: DNI: DNI; DigiKey: 296-18256-1-ND; DigiReel: 296-18256-6-ND; Family: logic; Index PN: 1027; Install: Y; Lead Style: SMT; MFG: Texas Instruments; P/D_NUM: SN74AUP1G07DCKR; Part Number: SN74AUP1G07DCKR; Part Specific: IC BUFF/DVR LOW PWR N-INV SC705, open drain; Type: buffer

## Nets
DGND: C89.2 C90.2 C91.2 C92.2 C93.2 C94.2 C95.2 C96.2 C97.2 C98.2 C99.2 C100.2 C103.2 C104.2 C105.2 C106.2 C107.2 C108.2 C109.2 C110.2 C111.2 C112.2 C113.2 C114.2 C115.2 C116.2 C117.2 C118.2 C119.2 C120.2 C121.2 C122.2 C123.2 C124.2 C125.2 C126.2 C127.2 C130.2 C131.2 C132.2 C175.2 C176.2 C177.2 C178.2 C179.2 C180.2 C181.2 C182.1 C183.1 C184.2 C185.1 C186.1 C187.1 C188.1 C189.1 C190.2 C191.2 C192.1 C193.2 C194.1 C195.1 C196.1 C197.1 C198.1 C199.1 C200.2 C201.1 C202.1 C203.1 C204.2 C205.2 C206.2 C207.2 C208.2 C209.1 C210.2 C211.1 C212.2 C213.1 C214.2 C215.1 C216.1 C217.1 C218.2 C219.1 C220.1 C221.1 C222.1 C223.1 C224.1 C225.1 C230.1(P) C231.1(P) C232.1(P) C233.2(N) C234.2(N) C235.2(N) C236.2(N) C237.2(N) C238.2(N) C239.2(N) C240.2(N) C241.2(N) C245.1 C246.2 C247.2 C248.1 C249.1 C250.2 C276.2 C277.2 C278.2 C279.2 C283.1 C284.2 C285.2 C286.2 C287.2 C288.2 C289.1 C405.2 ED1.A(ANODE) ED2.A(ANODE) ED3.A(ANODE) ED4.A(ANODE) ED5.A(ANODE) ED6.A(ANODE) ED7.A(ANODE) ED8.A(ANODE) ED9.A(ANODE) ED10.A(ANODE) ED11.A(ANODE) ED12.A(ANODE) ED17.A(ANODE) ED18.A(ANODE) ED38.A(ANODE) ED39.A(ANODE) ED40.A(ANODE) ED41.A(ANODE) ED42.A(ANODE) H1.1(H) H2.1(H) H3.1(H) H4.1(H) H5.1(H) H6.1(H) J18.5(TMDS_DATA1S) J18.8(TMDS_DATA0S) J18.11(TMDS_CLOCKS) J18.17(CEC_GND) J18.20(Shield) J18.21(Shield) J18.22(Shield) J18.23(Shield) J20.2 J22.1(P1) J22.4(P4) J22.7(P7) J22.12(P12) J22.17(P17) J22.20(P20) J22.25(P25) J22.28(P28) J22.31(P31) J22.36(P36) J22.38(P38) J22.45(P45) J22.50(P50) J22.52(P52) J22.57(P57) J22.62(P62) J22.65(P65) J22.70(P70) J22.75(P75) J22.80(P80) J22.81(P81) J22.82(P82) J23.3 J23.4 J23.5 J24.2 J26.2 J26.8 J26.9 J26.10 J34.9 L6.1 L8.1 R348.2 R354.2 R355.2 R375.1 R381.2 R436.2 R525.2 R785.2 SW21.3 SW21.4 U20.1(GND) U21.1(A0) U21.2(A1) U21.3(A2) U21.4(GND) U22.2(GND) U23.77(EXPOSED_GND_PAD) U24.2(GND) U29.2(GND) U34.14(AVSS1) U34.16(DVSS1) U34.39(DVSS2) U34.49(VSSU) U34.56(AVSS2) U34.65(Thermal_Pad) U39.C4(VSS) U39.C6(VSS) U39.C8(VSS) U39.D6(VSS) U39.D8(VSS) U39.D10(VSS) U39.E4(VSS) U39.E13(VSS) U39.F4(VSS) U39.F6(VSS) U39.F7(VSS) U39.F8(VSS) U39.F9(VSS) U39.F10(VSS) U39.G4(VSS) U39.G6(VSS) U39.G7(VSS) U39.G8(VSS) U39.G9(VSS) U39.G10(VSS) U39.G12(VSS) U39.G13(VSS) U39.H4(VSS) U39.H6(VSS) U39.H7(VSS) U39.H8(VSS) U39.H9(VSS) U39.H10(VSS) U39.H12(VSS) U39.J3(VSS) U39.J6(VSS) U39.J7(VSS) U39.J8(VSS) U39.J9(VSS) U39.J10(VSS) U39.J13(VSS) U39.K4(VSS) U39.K6(VSS) U39.K7(VSS) U39.K8(VSS) U39.K9(VSS) U39.K10(VSS) U39.K12(VSS) U39.L3(VSS) U39.M4(VSS) U39.M5(VSS) U39.M8(VSS) U39.M12(VSS) U40.C4(VSS) U40.C6(VSS) U40.C8(VSS) U40.D6(VSS) U40.D8(VSS) U40.D10(VSS) U40.E4(VSS) U40.E13(VSS) U40.F4(VSS) U40.F6(VSS) U40.F7(VSS) U40.F8(VSS) U40.F9(VSS) U40.F10(VSS) U40.G4(VSS) U40.G6(VSS) U40.G7(VSS) U40.G8(VSS) U40.G9(VSS) U40.G10(VSS) U40.G12(VSS) U40.G13(VSS) U40.H4(VSS) U40.H6(VSS) U40.H7(VSS) U40.H8(VSS) U40.H9(VSS) U40.H10(VSS) U40.H12(VSS) U40.J3(VSS) U40.J6(VSS) U40.J7(VSS) U40.J8(VSS) U40.J9(VSS) U40.J10(VSS) U40.J13(VSS) U40.K4(VSS) U40.K6(VSS) U40.K7(VSS) U40.K8(VSS) U40.K9(VSS) U40.K10(VSS) U40.K12(VSS) U40.L3(VSS) U40.M4(VSS) U40.M5(VSS) U40.M8(VSS) U40.M12(VSS) U67.3(GND) ; also on sheet 7 8 9 10 11 12
P5V: C179.1 C245.2 D32.G(A2) U20.3(IN) U22.5(VIN) U29.1(IN) U29.3(EN) ; also on sheet 8 10 11 12
VCC: C103.1 C104.1 C105.1 C106.1 C116.1 C117.1 C118.1 C119.1 C276.1 C277.1 C278.1 C279.1 R235.1 U39.C7(VCC) U39.C9(VCC) U39.D4(VCC) U39.E12(VCC) U39.F12(VCC) U39.K13(VCC) U39.M11(VCC) U40.C7(VCC) U40.C9(VCC) U40.D4(VCC) U40.E12(VCC) U40.F12(VCC) U40.K13(VCC) U40.M11(VCC)
VCC_INTF: C109.1 C111.1 C126.1 C127.1 C175.1 C176.1 C177.1 C178.1 R240.2 R241.1 R640.2 U39.M3(VCC_INTF) U39.M7(VCC_INTF) U39.N3(VCC_INTF) U39.N7(VCC_INTF) U40.M3(VCC_INTF) U40.M7(VCC_INTF) U40.N3(VCC_INTF) U40.N7(VCC_INTF)
VCC_TARGET: J34.4 R781.1
VCC_TOOL: J34.2 R779.1
VDD: C89.1 C90.1 C91.1 C92.1 C93.1 C94.1 C95.1 C96.1 C97.1 C98.1 C99.1 C100.1 C108.1 C110.1 C113.1 C114.1 C120.1 C121.1 C122.1 C123.1 C124.1 C125.1 C131.1 C132.1 L5.1 L7.1 R234.2 U39.C5(VDD) U39.D3(VDD) U39.D5(VDD) U39.D7(VDD) U39.D9(VDD) U39.D12(VDD) U39.D13(VDD) U39.E3(VDD) U39.F13(VDD) U39.H13(VDD) U39.J4(VDD) U39.J12(VDD) U39.K3(VDD) U39.L4(VDD) U39.L12(VDD) U39.L13(VDD) U39.M6(VDD) U39.M9(VDD) U39.M10(VDD) U40.C5(VDD) U40.D3(VDD) U40.D5(VDD) U40.D7(VDD) U40.D9(VDD) U40.D12(VDD) U40.D13(VDD) U40.E3(VDD) U40.F13(VDD) U40.H13(VDD) U40.J4(VDD) U40.J12(VDD) U40.K3(VDD) U40.L4(VDD) U40.L12(VDD) U40.L13(VDD) U40.M6(VDD) U40.M9(VDD) U40.M10(VDD)
VDD_PLL: C101.1 C102.1 L5.2 U39.H2(VDD_PLLM) U39.J2(VDD_PLLD)
VDDLP12: C107.1 R237.1 U39.C3(VDDLP12)
VINTF: R241.2 ; also on sheet 7 10
VSS_PLL: C101.2 C102.2 L6.2 U39.G3(VSS_PLLM) U39.H3(VSS_PLLD)
3DR_D: R376.1 TP149.1(P1) ; also on sheet 11
6801_DE: R360.1 U23.8(DE)
6801_HSYNC: R363.1 U23.9(HSYNC)
6801_PCLK: C204.1 R364.1 U23.75(PCLK)
6801_VSYNC: R361.1 R636.2 U23.10(VSYNC)
B_0: RP1.1 U23.5(QE4)
B_1: RP1.2 U23.4(QE5)
B_2: RP1.3 U23.3(QE6)
B_3: RP1.4 U23.2(QE7)
B_4: RP2.1 U23.1(QE8)
B_5: RP2.2 U23.74(QE9)
B_6: RP2.3 U23.73(QE10)
B_7: RP2.4 U23.72(QE11)
BLUE_S: R540.2 U34.21(P1.3/TA0.2)
CDSENSE: C191.1 J18.2(TMDS_DATA2S) R348.1 U23.19(CDSENSE)
CEC0: ED9.C(CATHODE) J18.13(CEC)
DATEN_CMD: R360.2 TP153.1(P1) ; also on sheet 9
DDC_SCL: ED11.C(CATHODE) J18.15(SCL) Q8.3(DRAIN) R352.2
DDCPWR: D32.S(A1) J18.18(+5V_POWER) R353.1 R366.2 R380.1
DDCSCL0: R356.2 U23.17(DDCSCL0)
DDCSDA0: R358.2 U23.16(DDCSDA0)
DMD_DEN_ARSTZ: J22.2(P2) U39.B1(DMD_DEN_ARSTZ)
DMD_HS_CLK_N: J22.19(P19) U39.B7(DMD_HS_CLK_N)
DMD_HS_CLK_P: J22.18(P18) U39.A7(DMD_HS_CLK_P)
DMD_HS_WDATAA_N: J22.9(P9) U39.B11(DMD_HS_WDATAA_N)
DMD_HS_WDATAA_P: J22.8(P8) U39.A11(DMD_HS_WDATAA_P)
DMD_HS_WDATAB_N: J22.11(P11) U39.B10(DMD_HS_WDATAB_N)
DMD_HS_WDATAB_P: J22.10(P10) U39.A10(DMD_HS_WDATAB_P)
DMD_HS_WDATAC_N: J22.14(P14) U39.B9(DMD_HS_WDATAC_N)
DMD_HS_WDATAC_P: J22.13(P13) U39.A9(DMD_HS_WDATAC_P)
DMD_HS_WDATAD_N: J22.16(P16) U39.B8(DMD_HS_WDATAD_N)
DMD_HS_WDATAD_P: J22.15(P15) U39.A8(DMD_HS_WDATAD_P)
DMD_HS_WDATAE_N: J22.22(P22) U39.B6(DMD_HS_WDATAE_N)
DMD_HS_WDATAE_P: J22.21(P21) U39.A6(DMD_HS_WDATAE_P)
DMD_HS_WDATAF_N: J22.24(P24) U39.B5(DMD_HS_WDATAF_N)
DMD_HS_WDATAF_P: J22.23(P23) U39.A5(DMD_HS_WDATAF_P)
DMD_HS_WDATAG_N: J22.27(P27) U39.B4(DMD_HS_WDATAG_N)
DMD_HS_WDATAG_P: J22.26(P26) U39.A4(DMD_HS_WDATAG_P)
DMD_HS_WDATAH_N: J22.30(P30) U39.B3(DMD_HS_WDATAH_N)
DMD_HS_WDATAH_P: J22.29(P29) U39.A3(DMD_HS_WDATAH_P)
DMD_LS_CLK: J22.3(P3) R114.1
DMD_LS_WDATA: J22.5(P5) R115.1
DMD_VBIAS: C230.2(N) C239.1(P) J22.43(P43) J22.44(P44) R415.1(N1)
DMD_VDD: C233.1(P) C234.1(P) C236.1(P) C237.1(P) J22.46(P46) J22.47(P47) J22.48(P48) J22.49(P49) R416.1(N1)
DMD_VOFS: C232.2(N) C241.1(P) J22.39(P39) J22.40(P40) R413.1(N1)
DMD_VRST: C231.2(N) C240.1(P) J22.41(P41) J22.42(P42) R414.1(N1)
DPP_P1P1V: R234.1 R237.2 R239.2 ; also on sheet 12
DPP_P1P8V: C235.1(P) C405.1 FB7.1 R235.2 R240.1 R416.2(N2) U67.5(PWR) ; also on sheet 9 10 11 12
DPP_VSYNC: R539.2 U34.26(P2.0/TA1.1)
EDID0_5V: C190.1 D32.D(K) R349.1 R350.1 R351.1 R352.1 R365.2 U21.8(VDD)
EDID_WP: J20.1 R351.2 R354.1 U21.7(WP)
ENVBUS#: Q8.1(GATE) R365.1 TP89.1(TP) U22.4(/EN) U23.11(ENVBUS#)
EXT_M_SPI_CLK: J22.35(P35) ; also on sheet 10
EXT_M_SPI_CSZ: J22.32(P32) ; also on sheet 10
EXT_M_SPI_DIN: J22.33(P33) ; also on sheet 10
EXT_M_SPI_DOUT: J22.34(P34) ; also on sheet 10
EXT_S_SPI_CLK: J22.79(P79) ; also on sheet 10
EXT_S_SPI_CSZ: J22.76(P76) ; also on sheet 10
EXT_S_SPI_DIN: J22.77(P77) ; also on sheet 10
EXT_S_SPI_DOUT: J22.78(P78) ; also on sheet 10
Fan1_Lock: R430.1 ; also on sheet 8
FAN1_PWM: R631.1 ; also on sheet 8
Fan2_Lock: R504.2 ; also on sheet 8
FAN2_PWM: R630.1 ; also on sheet 8
FLASH_PWR: C238.1(P) J22.37(P37) R417.1(N1)
G_0: RP3.1 U23.69(QE16)
G_1: RP3.2 U23.68(QE17)
G_2: RP3.3 U23.67(QE18)
G_3: RP3.4 U23.66(QE19)
G_4: RP4.1 U23.65(QE20)
G_5: RP4.2 U23.62(QE21)
G_6: RP4.3 U23.61(QE22)
G_7: RP4.4 U23.60(QE23)
GREEN_S: R541.2 U34.20(P1.2/TA0.1)
HSYNC_CS: R363.2 TP151.1(P1) ; also on sheet 9
IIC0_SCL: R379.2 R451.1 R533.1 R536.1 TP249.1(P1) ; also on sheet 7 10
IIC0_SDA: R377.2 R452.2 R534.1 R535.1 TP248.1(P1) ; also on sheet 7 10
IT6801_INTN: R368.2 R431.1 TP88.1(TP)
IT6801_RSTN: R359.1 R505.2 TP86.1(TP)
IT6801_VSYNC: R636.1 R644.2
LDO_P3P3V: C181.1 C184.1 C200.1 FB1.2 FB2.1 FB3.1 FB4.2 FB5.1 FB6.1 R624.2
LED_SYS_ON-OFF: R437.1 U34.41(P4.0/PM_UCB1STE/PM_UCA1CLK)
LS_CLK: R114.2 U39.A1(DMD_LS_CLK)
LS_RDATA: R116.2 U39.B2(DMD_LS_RDATA)
LS_WDATA: R115.2 U39.A2(DMD_LS_WDATA)
M_HOST_IRQ: U34.12(P5.4/XIN) ; also on sheet 7 9
M_LS_RDATA: J22.6(P6) R116.1
MCU_ACK: R774.1 ; also on sheet 7
MCU_DPP_RST: R425.1 ; also on sheet 10
MCU_M_SCL: R530.1 R533.2 U34.43(P4.2/PM_UCB1SOMI/PM_UCB1SCL)
MCU_M_SDA: R529.1 R534.2 U34.42(P4.1/PM_UCB1SIMO/PM_UCB1SDA)
MCU_P3.2: ED17.C(CATHODE) J24.1 R433.2 R629.1 TP158.1(P1) ; also on sheet 7
MCU_P3.3: ED18.C(CATHODE) J24.3 R432.2 R632.2 TP159.1(P1) ; also on sheet 7
MCU_REQ: R775.1 ; also on sheet 7
MCU_SW_ONOFF: R641.2 ; also on sheet 7
MCU_USB_DM: TP246.1(P1) U34.52(PU.1/DM)
MCU_USB_DP: TP247.1(P1) U34.50(PU.0/DP)
MSP430_S_SCL: R536.2 R537.1 TP129.1(P1) ; also on sheet 7 10
MSP430_S_SDA: R535.2 R538.1 TP128.1(P1) ; also on sheet 7 10
MSP_PROJ_ON: R435.1 R436.1 TP107.1(TP) ; also on sheet 8
MSP_V3P3V: C285.1 C286.1 C287.1 C288.1 D36.1(ANODE) D44.1(ANODE) D45.1(ANODE) D46.1(ANODE) R443.1(N1) R521.2 R524.1 R529.2 R530.2 R779.2 R781.2 R784.2 U34.11(AVCC1) U34.15(DVCC1) U34.40(DVCC2)
P3P3V: C249.2 C250.1 FB4.1 J26.1 R242.2 R243.2 R418.1 R432.1 R433.1 R623.2 R790.2(N2) R791.2(N2) R792.2(N2) R817.2 ; also on sheet 7 8 9 10 11 12
P3P3V_INTF: R640.1 ; also on sheet 11 12
P3P3V_PWR_EN: R646.1 ; also on sheet 8
PCLK: C205.1 R364.2 TP152.1(P1) ; also on sheet 9
PCSCL: R379.1 R486.1 U23.14(PCSCL)
PCSDA: R377.1 R485.1 U23.13(PCSDA)
PDATA0: RP1.8 ; also on sheet 9
PDATA1: RP1.7 ; also on sheet 9
PDATA2: RP1.6 ; also on sheet 9
PDATA3: RP1.5 ; also on sheet 9
PDATA4: RP2.8 ; also on sheet 9
PDATA5: RP2.7 ; also on sheet 9
PDATA6: RP2.6 ; also on sheet 9
PDATA7: RP2.5 ; also on sheet 9
PDATA16: RP5.8 ; also on sheet 9
PDATA17: RP5.7 ; also on sheet 9
PDATA18: RP5.6 ; also on sheet 9
PDATA19: RP5.5 ; also on sheet 9
PDATA20: RP6.8 ; also on sheet 9
PDATA21: RP6.7 ; also on sheet 9
PDATA22: RP6.6 ; also on sheet 9
PDATA23: RP6.5 ; also on sheet 9
PDATA_8: RP3.8 ; also on sheet 9
PDATA_9: RP3.7 ; also on sheet 9
PDATA_10: RP3.6 ; also on sheet 9
PDATA_11: RP3.5 ; also on sheet 9
PDATA_12: RP4.8 ; also on sheet 9
PDATA_13: RP4.7 ; also on sheet 9
PDATA_14: RP4.6 ; also on sheet 9
PDATA_15: RP4.5 ; also on sheet 9
PROJ_ON_MCU: R435.2 U34.18(P1.0/TA0CLK/ACLK)
R_0: RP5.1 U23.59(QE28)
R_1: RP5.2 U23.58(QE29)
R_2: RP5.3 U23.57(QE30)
R_3: RP5.4 U23.56(QE31)
R_4: RP6.1 U23.54(QE32)
R_5: RP6.2 U23.53(QE33)
R_6: RP6.3 U23.52(QE34)
R_7: RP6.4 U23.51(QE35)
RED_S: R542.2 U34.19(P1.1/TA0.0)
RST_NMI: J34.11 R782.2
RST_SBWTDIO: C284.1 J23.1 R524.2 R780.1 R782.1 U34.64(\\~{RS}T/NMI/SBWTDIO)
RX0+: ED5.C(CATHODE) J18.7(TMDS_DATA0+) R370.2 U23.29(P0_RX0P)
RX0-: ED6.C(CATHODE) J18.9(TMDS_DATA0-) R370.1 U23.28(P0_RX0N)
RX1+: ED3.C(CATHODE) J18.4(TMDS_DATA1+) R372.2 U23.32(P0_RX1P)
RX1-: ED4.C(CATHODE) J18.6(TMDS_DATA1-) R372.1 U23.31(P0_RX1N)
RX2+: ED1.C(CATHODE) J18.1(TMDS_DATA2+) R369.2 U23.34(P0_RX2P)
RX2-: ED2.C(CATHODE) J18.3(TMDS_DATA2-) R369.1 U23.33(P0_RX2N)
RX_1V2: C207.1 FB8.1 FB9.1 FB10.1 FB11.1 FB12.1 U24.5(VOUT)
RX_APVDD12: C214.1 C215.2 FB11.2 U23.37(APVDD12)
RX_AVCC12: C212.1 C213.2 FB10.2 U23.22(AVCC12)
RX_AVCC33: C185.2 C186.2 C187.2 C188.2 C189.2 FB3.2 U23.25(AVCC33) U23.30(AVCC33) U23.35(AVCC33) U23.40(APVCC33)
RX_DDCSCL: Q8.2(SOURCE) R350.2 R356.1 U21.6(SCL)
RX_DDCSDA: ED12.C(CATHODE) J18.16(SDA) R349.2 R358.1 U21.5(SDA)
RX_DVDD12: C208.1 C209.2 FB8.2 U23.36(DVDD12)
RX_HPD0: ED10.C(CATHODE) J18.19(Hot_Plug) R353.2 R355.1 R362.1
RX_IVDD12: C218.1 C219.2 C220.2 C221.2 C222.2 C223.2 C224.2 FB12.2 U23.7(IVDD12) U23.15(IVDD12) U23.43(IVDD12) U23.48(IVDD12) U23.64(IVDD12) U23.71(IVDD12)
RX_OVDD: C192.2 C193.1 C194.2 C195.2 C196.2 C197.2 C198.2 C199.2 FB5.2 FB7.2 R357.2 R367.2 R374.1 U23.6(OVDD) U23.50(OVDD) U23.55(OVDD) U23.63(OVDD) U23.70(OVDD) U23.76(OVDD)
RX_OVDD33: C182.2 C183.2 FB2.2 R485.2 R486.2 U23.20(OVDD33)
RX_PVCC12: C210.1 C211.2 FB9.2 U23.23(PVCC12)
RX_PVCC33: C201.2 C202.2 FB6.2 U23.24(PVCC33)
RXC+: ED7.C(CATHODE) J18.10(TMDS_CLOCK+) R371.2 U23.27(P0_RXCP)
RXC-: ED8.C(CATHODE) J18.12(TMDS_CLOCK-) R371.1 U23.26(P0_RXCN)
S-LS-RDATA: R109.2 U40.B2(DMD_LS_RDATA)
S_DMD_HS_CLK_N: J22.64(P64) U40.B7(DMD_HS_CLK_N)
S_DMD_HS_CLK_P: J22.63(P63) U40.A7(DMD_HS_CLK_P)
S_DMD_HS_WDATAA_N: J22.54(P54) U40.B11(DMD_HS_WDATAA_N)
S_DMD_HS_WDATAA_P: J22.53(P53) U40.A11(DMD_HS_WDATAA_P)
S_DMD_HS_WDATAB_N: J22.56(P56) U40.B10(DMD_HS_WDATAB_N)
S_DMD_HS_WDATAB_P: J22.55(P55) U40.A10(DMD_HS_WDATAB_P)
S_DMD_HS_WDATAC_N: J22.59(P59) U40.B9(DMD_HS_WDATAC_N)
S_DMD_HS_WDATAC_P: J22.58(P58) U40.A9(DMD_HS_WDATAC_P)
S_DMD_HS_WDATAD_N: J22.61(P61) U40.B8(DMD_HS_WDATAD_N)
S_DMD_HS_WDATAD_P: J22.60(P60) U40.A8(DMD_HS_WDATAD_P)
S_DMD_HS_WDATAE_N: J22.67(P67) U40.B6(DMD_HS_WDATAE_N)
S_DMD_HS_WDATAE_P: J22.66(P66) U40.A6(DMD_HS_WDATAE_P)
S_DMD_HS_WDATAF_N: J22.69(P69) U40.B5(DMD_HS_WDATAF_N)
S_DMD_HS_WDATAF_P: J22.68(P68) U40.A5(DMD_HS_WDATAF_P)
S_DMD_HS_WDATAG_N: J22.72(P72) U40.B4(DMD_HS_WDATAG_N)
S_DMD_HS_WDATAG_P: J22.71(P71) U40.A4(DMD_HS_WDATAG_P)
S_DMD_HS_WDATAH_N: J22.74(P74) U40.B3(DMD_HS_WDATAH_N)
S_DMD_HS_WDATAH_P: J22.73(P73) U40.A3(DMD_HS_WDATAH_P)
S_HOST_IRQ: U34.13(P5.5/XOUT) ; also on sheet 7 9
S_LS_RDATA: J22.51(P51) R109.1
S_VDD_PLL: C128.1 C129.1 L7.2 U40.H2(VDD_PLLM) U40.J2(VDD_PLLD)
S_VDDLP12: C115.1 R239.1 U40.C3(VDDLP12)
S_VFLSH: C130.1 R243.1 U40.D11(VCC_FLSH) ; also on sheet 7 10
S_VSS_PLL: C128.2 C129.2 L8.2 U40.G3(VSS_PLLM) U40.H3(VSS_PLLD)
SEN_BOUT: ED41.C(CATHODE) J26.5 R540.1 R792.1(N1) TP157.1(P1)
SEN_GOUT: ED42.C(CATHODE) J26.4 R541.1 R791.1(N1) TP156.1(P1)
SEN_ROUT: ED38.C(CATHODE) J26.3 R542.1 R790.1(N1) TP155.1(P1)
SPI_BUS_SEL: R427.2 ; also on sheet 10
STDBY_PWR: C247.1 R419.1 TP106.1 U29.5(OUT)
SW_SYS_ON-OFF: C248.2 R443.2(N2) R447.1(N1) TP115.1(P1) U34.1(P6.0/CB0/A0) ; also on sheet 10
SYSRSTN: C203.2 R357.1 R359.2 U23.47(SYSRSTN)
TCK: J34.7 R783.1 U34.63(PJ.3/TCK)
TDI: J34.3 U34.61(PJ.1/TDI/TCLK)
TDO: R778.1 U34.60(PJ.0/TDO)
TEST_SBWTCK: J23.2 J34.8 R783.2 U34.59(TEST/SBWTCK)
TMS: J34.5 U34.62(PJ.2/TMS)
TRIG_IN: R643.1 TP108.1(TP)
TRIG_IN_A_S: R643.2 U34.22(P1.4/TA0.3)
TRIG_IN_B_S: R644.1 U34.23(P1.5/TA0.4)
TSTPT2: U67.2(A) ; also on sheet 10 11
VBIAS: R415.2(N2) ; also on sheet 12
VFLSH: C112.1 R242.1 R417.2(N2) U39.D11(VCC_FLSH) ; also on sheet 10
VOFS: R413.2(N2) ; also on sheet 12
VRST: R414.2(N2) ; also on sheet 12
VSYNC_WE: R361.2 TP150.1(P1) ; also on sheet 9
N25435391: C180.1 FB1.1 U20.2(VOUT) U20.4(VOUT)
N25435732: J18.14(RESERVED) TP85.1(TP)
N25435921: C206.1 R373.2 R623.1 R624.1 U24.1(VIN)
N25435945: R373.1 U24.3(EN)
N25436119: C225.2 R380.2 R381.1 U23.18(R0PWR5V)
N25436359: TP91.1 U23.45(WS_SPDIF)
N25437005: R367.1 R368.1 U23.12(INT#_CEC)
N25437156: R362.2 U23.21(CBUS/HPD)
N25437172: R376.2 U23.44(I2S1_3DR)
N25437209: C216.2 R378.1 U23.38(XTALOUT) Y1.1
N25437221: TP92.1 U23.46(SCK_MCLK)
N25437238: TP93.1 U23.41(MUTE_MCLK)
N25437244: TP90.1 U23.42(I2S0)
N25437248: C217.2 R378.2 U23.39(XTALIN) Y1.2
N25946232: TP87.1 U22.3(/OC)
N25946248: R366.1 U22.1(VOUT)
N29844069: D46.2(CATHODE) R528.1
N29846093: D45.2(CATHODE) R527.1
N29846811: D44.2(CATHODE) R526.1
N29846839: R528.2 U34.6(P6.5/CB5/A5)
N29846850: R527.2 U34.7(P6.6/CB6/A6)
N29847556: R526.2 U34.8(P6.7/CB7/A7)
N29892842: R784.1 R785.1 U34.51(PUR)
N29894404: R525.1 U34.53(VBUS)
N29895084: C283.2 U34.54(VUSB)
N29895588: TP111.1(P1) U34.55(V18)
N29895905: R425.2 U34.57(P5.2/XT2IN)
N29896007: R427.1 U34.58(P5.3/XT2OUT)
N29902454: R646.2 U34.38(P3.4/UCA0RXD/UCA0SOMI)
N29902570: R632.1 U34.37(P3.3/UCA0TXD/UCA0SIMO)
N29902811: R629.2 U34.36(P3.2/UCB0CLK/UCA0STE)
N29903191: R538.2 U34.34(P3.0/UCB0SIMO/UCB0SDA)
N30048506: R774.2 U34.24(P1.6/TA1CLK/CBOUT)
N30048649: R775.2 U34.25(P1.7/TA1.0)
N30049990: R504.1 U34.29(P2.3/TA2.0)
N30050137: R631.2 U34.30(P2.4/TA2.1)
N30050285: R630.2 U34.31(P2.5/TA2.2)
N30050434: R431.2 U34.32(P2.6/RTCCLK/DMAE0)
N39097418: J34.1 R778.2 R780.2
N39165630: D36.2(CATHODE) R437.2
N39165678: R447.2(N2) SW21.1 SW21.2
N39611008: R430.2 U34.27(P2.1/TA1.2)
N39819044: R505.1 U34.28(P2.2/TA2CLK/SMCLK)
N40047441: C246.1 U29.4(NC)
N40051597: R418.2 R419.2 R521.1
N40523145: ED39.C(CATHODE) J26.6 R452.1
N40523623: ED40.C(CATHODE) J26.7 R451.2
N40975177: TP250.1(P1) U34.2(P6.1/CB1/A1)
N40977066: TP251.1(P1) U34.3(P6.2/CB2/A2)
N40977534: TP252.1(P1) U34.4(P6.3/CB3/A3)
N40978003: TP253.1(P1) U34.5(P6.4/CB4/A4)
N40979427: TP254.1(P1) U34.9(P5.0/A8/VeREF+)
N40979898: TP255.1(P1) U34.10(P5.1/A9/VeREF-)
N40983206: TP256.1(P1) U34.48(P4.7/PM_NONE)
N40985599: TP257.1(P1) U34.47(P4.6/PM_NONE)
N40986073: TP258.1(P1) U34.46(P4.5/PM_UCA1RXD/PM_UCA1SOMI)
N40986548: TP259.1(P1) U34.45(P4.4/PM_UCA1TXD/PM_UCA1SIMO)
N40987024: TP260.1(P1) U34.44(P4.3/PM_UCB1CLK/PM_UCA1STE)
N43163776: R374.2 R375.2 U23.49(PCADR)
N45361543: C289.2 U34.17(VCORE)
N45389785: R641.1 U34.33(P2.7/UCB0STE/UCA0CLK)
N45410354: R537.2 U34.35(P3.1/UCB0SOMI/UCB0SCL)
N48652001: R539.1 R817.1 U67.4(Y)

Not connected (* = marked no-connect by the designer): J34 6* 10* 12* 13* 14*; U24 4(NC)*; U40 A1(DMD_LS_CLK)* A2(DMD_LS_WDATA)* B1(DMD_DEN_ARSTZ)*

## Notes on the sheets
sheet 1
- Core Power
- SLAVE
- MASTER
- SLAVE
- MASTER
- DLP018
sheet 2
- SOT23-5
- Spy-Bi-2 Wire  CONN
- -->DLPC3439
- (Master I2C)
- <--Ext I2C
- (Slave I2C)
- MCU GPIO
- Color Sensr I/F
- ON/OFF Button
- DLP018
sheet 3
- Version
- Release Date
- History
- T0
- 2018/02/09
- 1. First release.
- 2. Modify Trigger Signals base on  DLPDLCR4710EVM-G2 REV B
- 3. The GPIO_5 signal switch to the 3DR pin
- 4. PCB--00.LH908G001 REV A
- 1. DLPC3479 : GPIO_6 from the Slave has to be connected to the GPIO_5 on the Master
- A
- 2018/09/28
- 2. Add J9 Connector for Sensing function.
- 3. Add U68 for level shit function.
- 1. Change U68 from SN74AUP1G07DCK to SN74AUP1T17DCK
- B
- 2018/12/18
- 2. U52,U53,U54,U55,U56,U57,U58,U59,U60,U61,U66 will change
      from SN74AUP1G07DCK to SN74LVC1G07DCK
- 1. Updated Block Diagram description for M_TSTPT5 on header
- B.1
- 2022/03/18
- DLP018
sheet 4
- Block Diagram
- JTAG
  CONN
- P3P3V
- FAN1,2_PWM
- Color
  Sensor
  CONN
- Fan1,2_Lock
- SEN_R,SEN_G,SEN_B
- P1P1V
- TRIG_IN_1,2
- P1P8V
- MCU
  (MSP430F5514)
- ON/OFF
  Button
- VIN
- VINTF
- TEMP
  CONN
- SPI_BUS_OE
- PROJ_ON
- SENS2
- SPI_BUS_SEL
- VIN
- LED_Anode
- LED
  CONN
  (Red)
- OEZ
- S
- I2C
- R_CTRL
- 4
- M_SPI_0
- PMIC&
  LED
  Driver
  DLPA3005
- R_CATHD
- SPI
  CONN
- 4
- SPI
- 4Bits
  MUX/
  DEMUX
- P1P1V
- I2C_0
- GPIO8
- Vcore
- P1P8V
- 3DR
- G_CTRL
- VIO
- 3DR
- 4
- S_SPI_0
- VINTF
- LED
  CONN
  (Green)
- VINTF
- SPI(4)
- Power
  MOSFETs
- Master OSC
- SPI_1
- B_CTRL
- OSC.
  24MHz
- G_CATHD
- RESETZ
- RESETZ
- Slave OSC
- INTZ
- PARKZ
- INTZ
- LED
  CONN
  (Blue)
- M_SPI_0
- DLPC3479
  (Master)
- RLIM
- 3DR_D
- P3P3V
- LED_SEL(2)
- B_CATHD
- SPI Flash
  (64Mbit)
- SPI_0
- CMP_PWM
- RX0-,RX0+
  RX1-,RX1+
  RX2-,RX2+
  RXC-,RXC+
- CMP_OUT
- Vbias,Vofs,Vrst
- 24
- PDATA0~23
- HDMI
  CONN
- DPP_SYNC_OUT
- HDMI
  Receiver
- PCLK,DE,Vsyn,Hsyn
- 18
- Sub-LVDS Data,CLK
- DMD
    FPC
    CONN
    (80Pin)
- 4
- CTRLs
- IT6801_VSYNC_OUT
- I2C_1
- CTRLs
- 18
- Sub-LVDS Data,CLK
- CY_I2C
- Level
  Translator
- I2C
- I2C_0
- Mini
  USB
  CONN
- 4
- CTRLs
- USB
- CY_OE
- Cypress
  CY7C65215
  -32LTXI
- CY_SPI
- Bus
  Transceiver
- M_SPI_0
- RESETZ
- RESETZ
- (From DLPA3005)
- INTZ
- PARKZ
- Bus
  Transceiver
- S_SPI_0
- Slave OSC
- P12V
- Fan1_PWM
- Fan 1
  CONN
- DLPC3479
  (Slave)
- I2C
  CONN
- I2C
- FAN1_PWM
- Fan1_Lock
- S_SPI_0
- Fan Driver
    Circuit
- P3P3V
- FAN2_PWM
- SPI Flash
  (64Mbit)
- Fan2_PWR
- SPI_0
- Fan 2
  CONN
- TSTPT2_M
- 1x3 Pin
  Header
- Fan2_Lock
- 3DR_SA
- P1P1V
- PWR_TP_SEN
- Vcore
- P1P8V
- VIO
- 3DR_D
- TRIG_IN(3DR_S)
- VINTF
- VINTF
- P12V
- Fan 3
  CONN
- Pattern Ready(M_GPIO_06)
- 1x8 Pin
  Header
- TRIG_OUT_1(M_TSTP_4)
- Reserved(M_TSTP_7)
- Reserved(M_TSTP_6)
- TRIG_OUT_2(M_GPIO7)
- IO-1.8V
- 3DR_S
- 1x3 Pin
  Header
- IO_PWR_Sel
- 1x3 Pin
  Header
- 3DR
- 1x8 Pin
  Header
- Reserved(M_TSTP_3)
- Reserved (M_TSTP_5)
- Reserved(M_TSTP_2)
- IO-3.3V
- 3DR_D
- Reserved(M_TSTP_1)
- Reserved(M_TSTP_0)
- PWR_TP_SEN
- P19V
  Power
  Jack
- Step-Down
  Converter
  (TPS54335A)
- Step-Down
  Converter
  (TLV62565)
- VIN
- P12V
- LDO
  (LM2940-5)
- P5V
- P3P3V
- DLP018
sheet 5
- SLAVE
- Single end 68£[¡Ó10%
- Slave DMD Signals
- (10V)
- Differential 100£[¡Ó10%
- (-14V)
- (+18V)
- (-14V)
- (10V)
- (+18V)
- MASTER
- Single end 68£[¡Ó10%
  and R114 and R115 closed ASIC pins.
- Master DMD Signals
- Differential 100£[¡Ó10%
- DLP018
sheet 6
- EDID EEPROM
  Addr:A0
- HDMI CNNT
- Differential pairs
  Impedance =100 £[
- (PDATA0/Blue_0)
- (PDATA1/Blue_1)
- (PDATA2/Blue_2)
- (PDATA3/Blue_3)
- (PDATA4/Blue_4)
- (PDATA5/Blue_5)
- Screw Hole
- (PDATA6/Blue_6)
- (PDATA7/Blue_7)
- Close to HDMI connector corresponding pin.
- (PDATA8/Green_0)
- (PDATA9/Green_1)
- (PDATA10/Green_2)
- (PDATA11/Green_3)
- (PDATA12/Green_4)
- (PDATA13/Green_5)
- (PDATA14/Green_6)
- Addr. 0x90
- (PDATA15/Green_7)
- (PDATA16/Red_0)
- (PDATA17/Red_1)
- (PDATA18/Red_2)
- (PDATA19/Red_3)
- SOT23-5
- (PDATA20/Red_4)
- (PDATA21/Red_5)
- (PDATA22/Red_6)
- (PDATA23/Red_7)
- DLP018
